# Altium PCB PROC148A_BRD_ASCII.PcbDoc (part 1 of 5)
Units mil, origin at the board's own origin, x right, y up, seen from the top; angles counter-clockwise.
Board outline 7150 x 3764 mil, 4 copper layers (Top Layer, GND01, PWR/GND02, Bottom Layer), stack 60.96 mil thick; 312 components, 352 nets, 2206 pads, 423 vias.
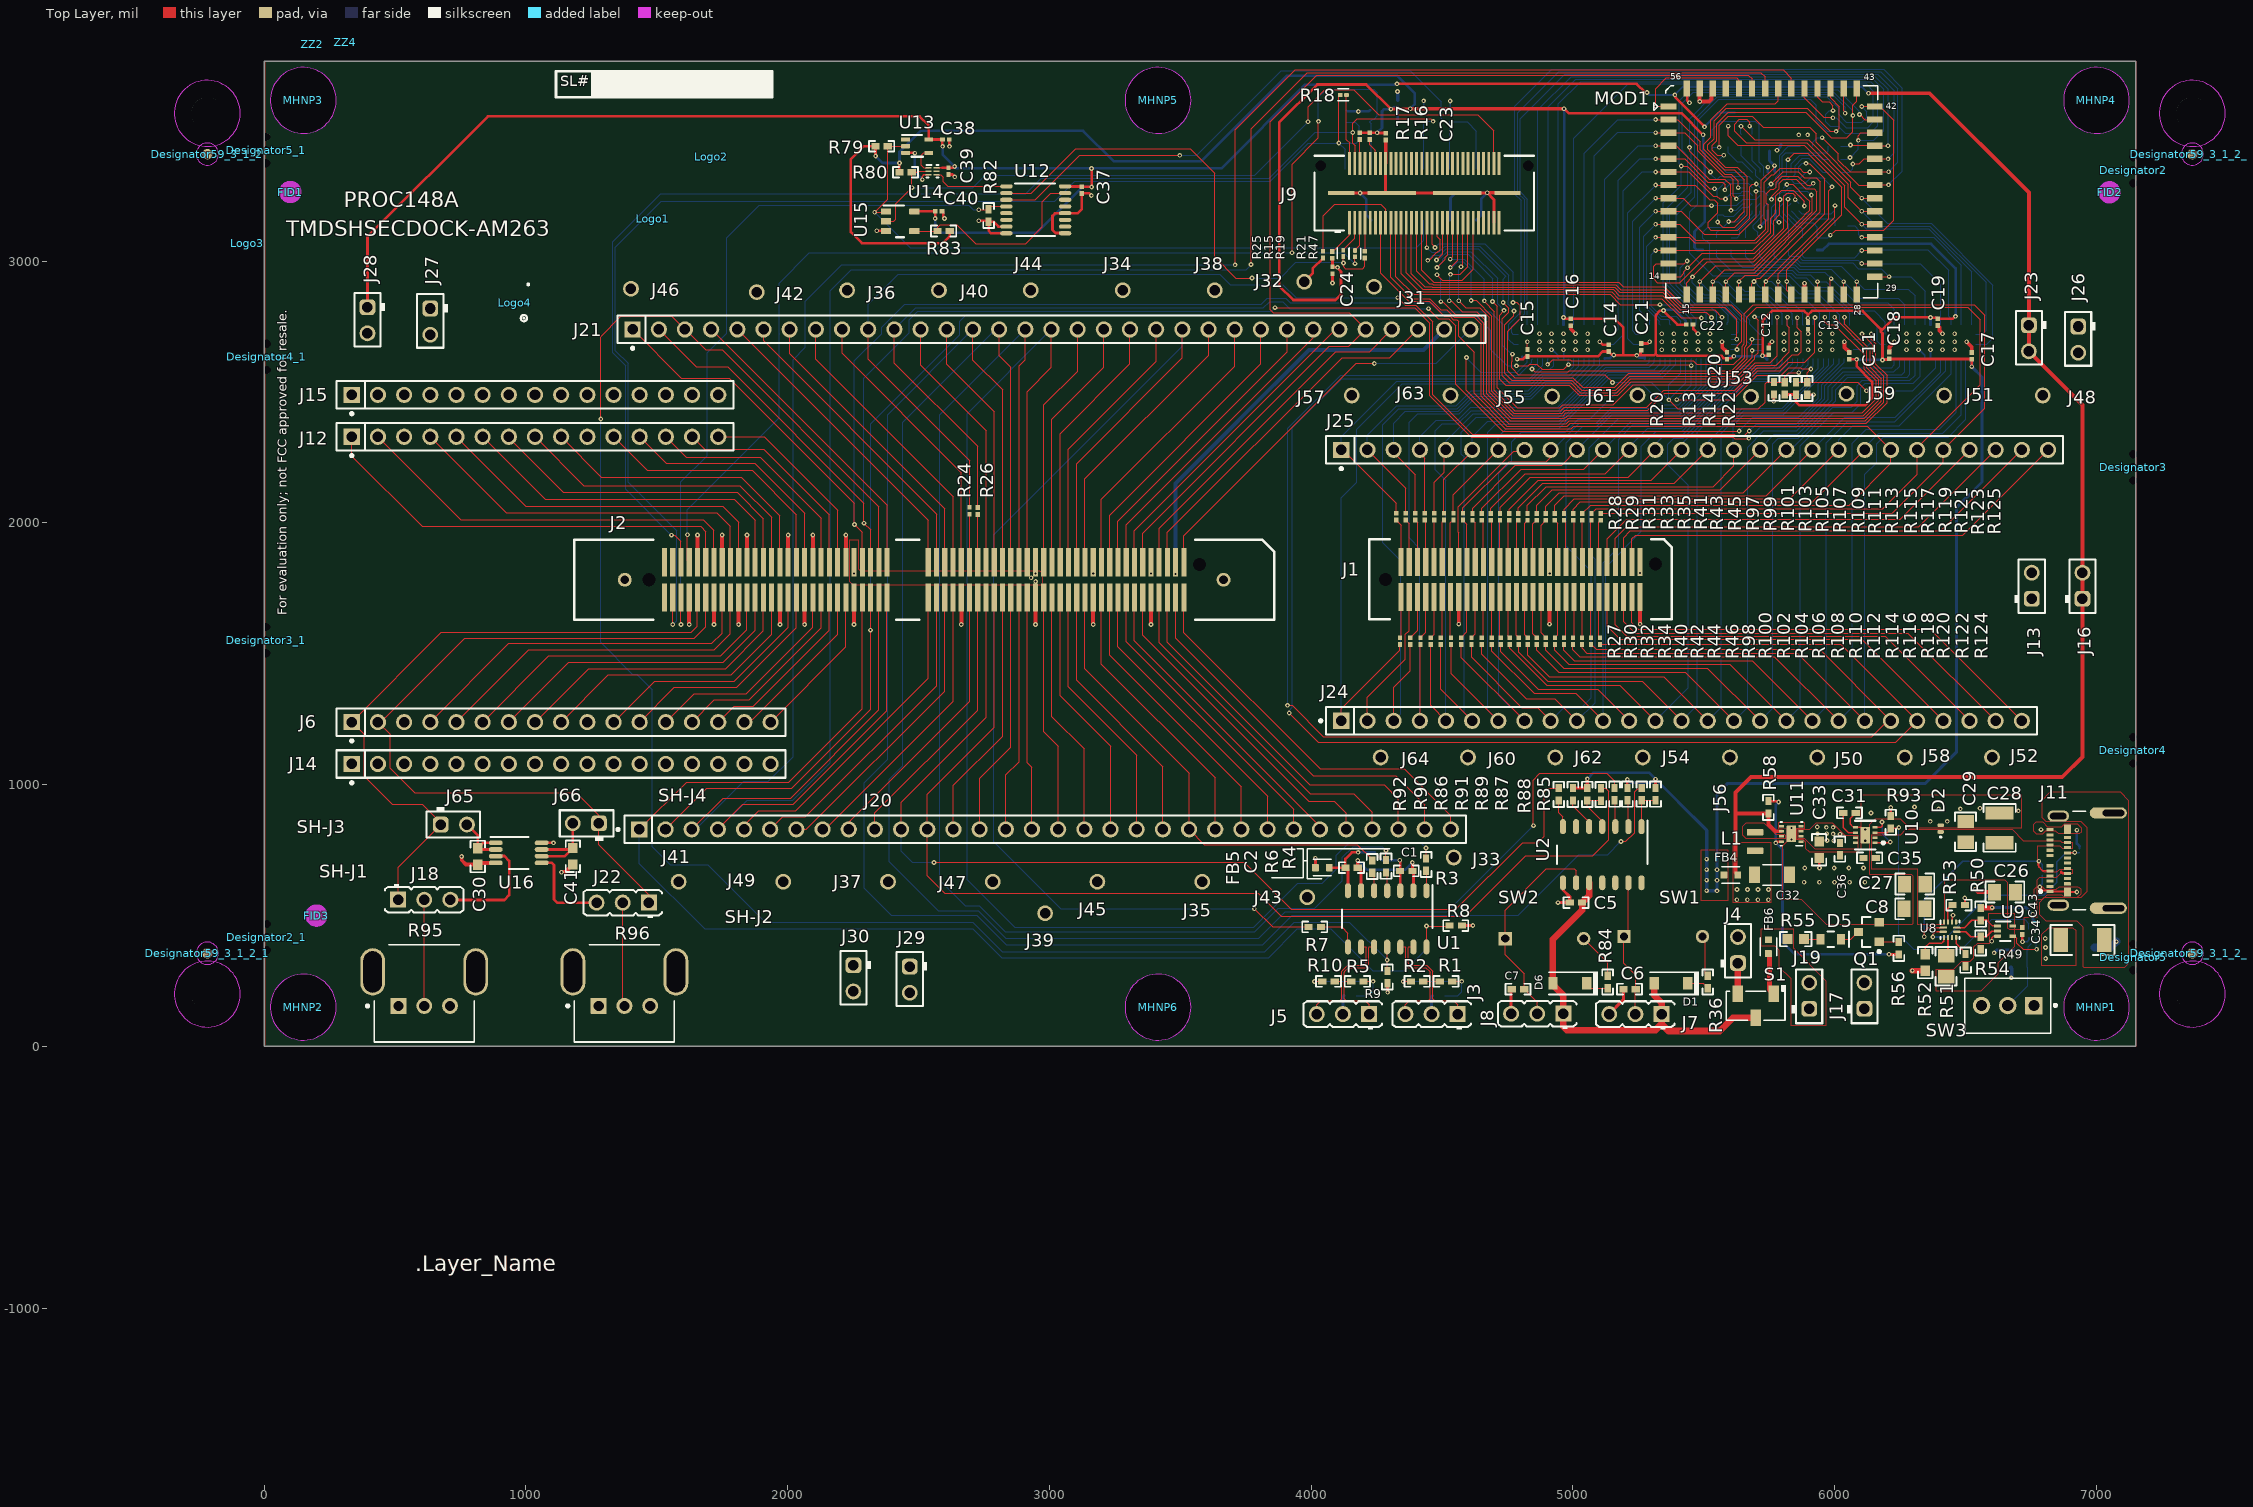
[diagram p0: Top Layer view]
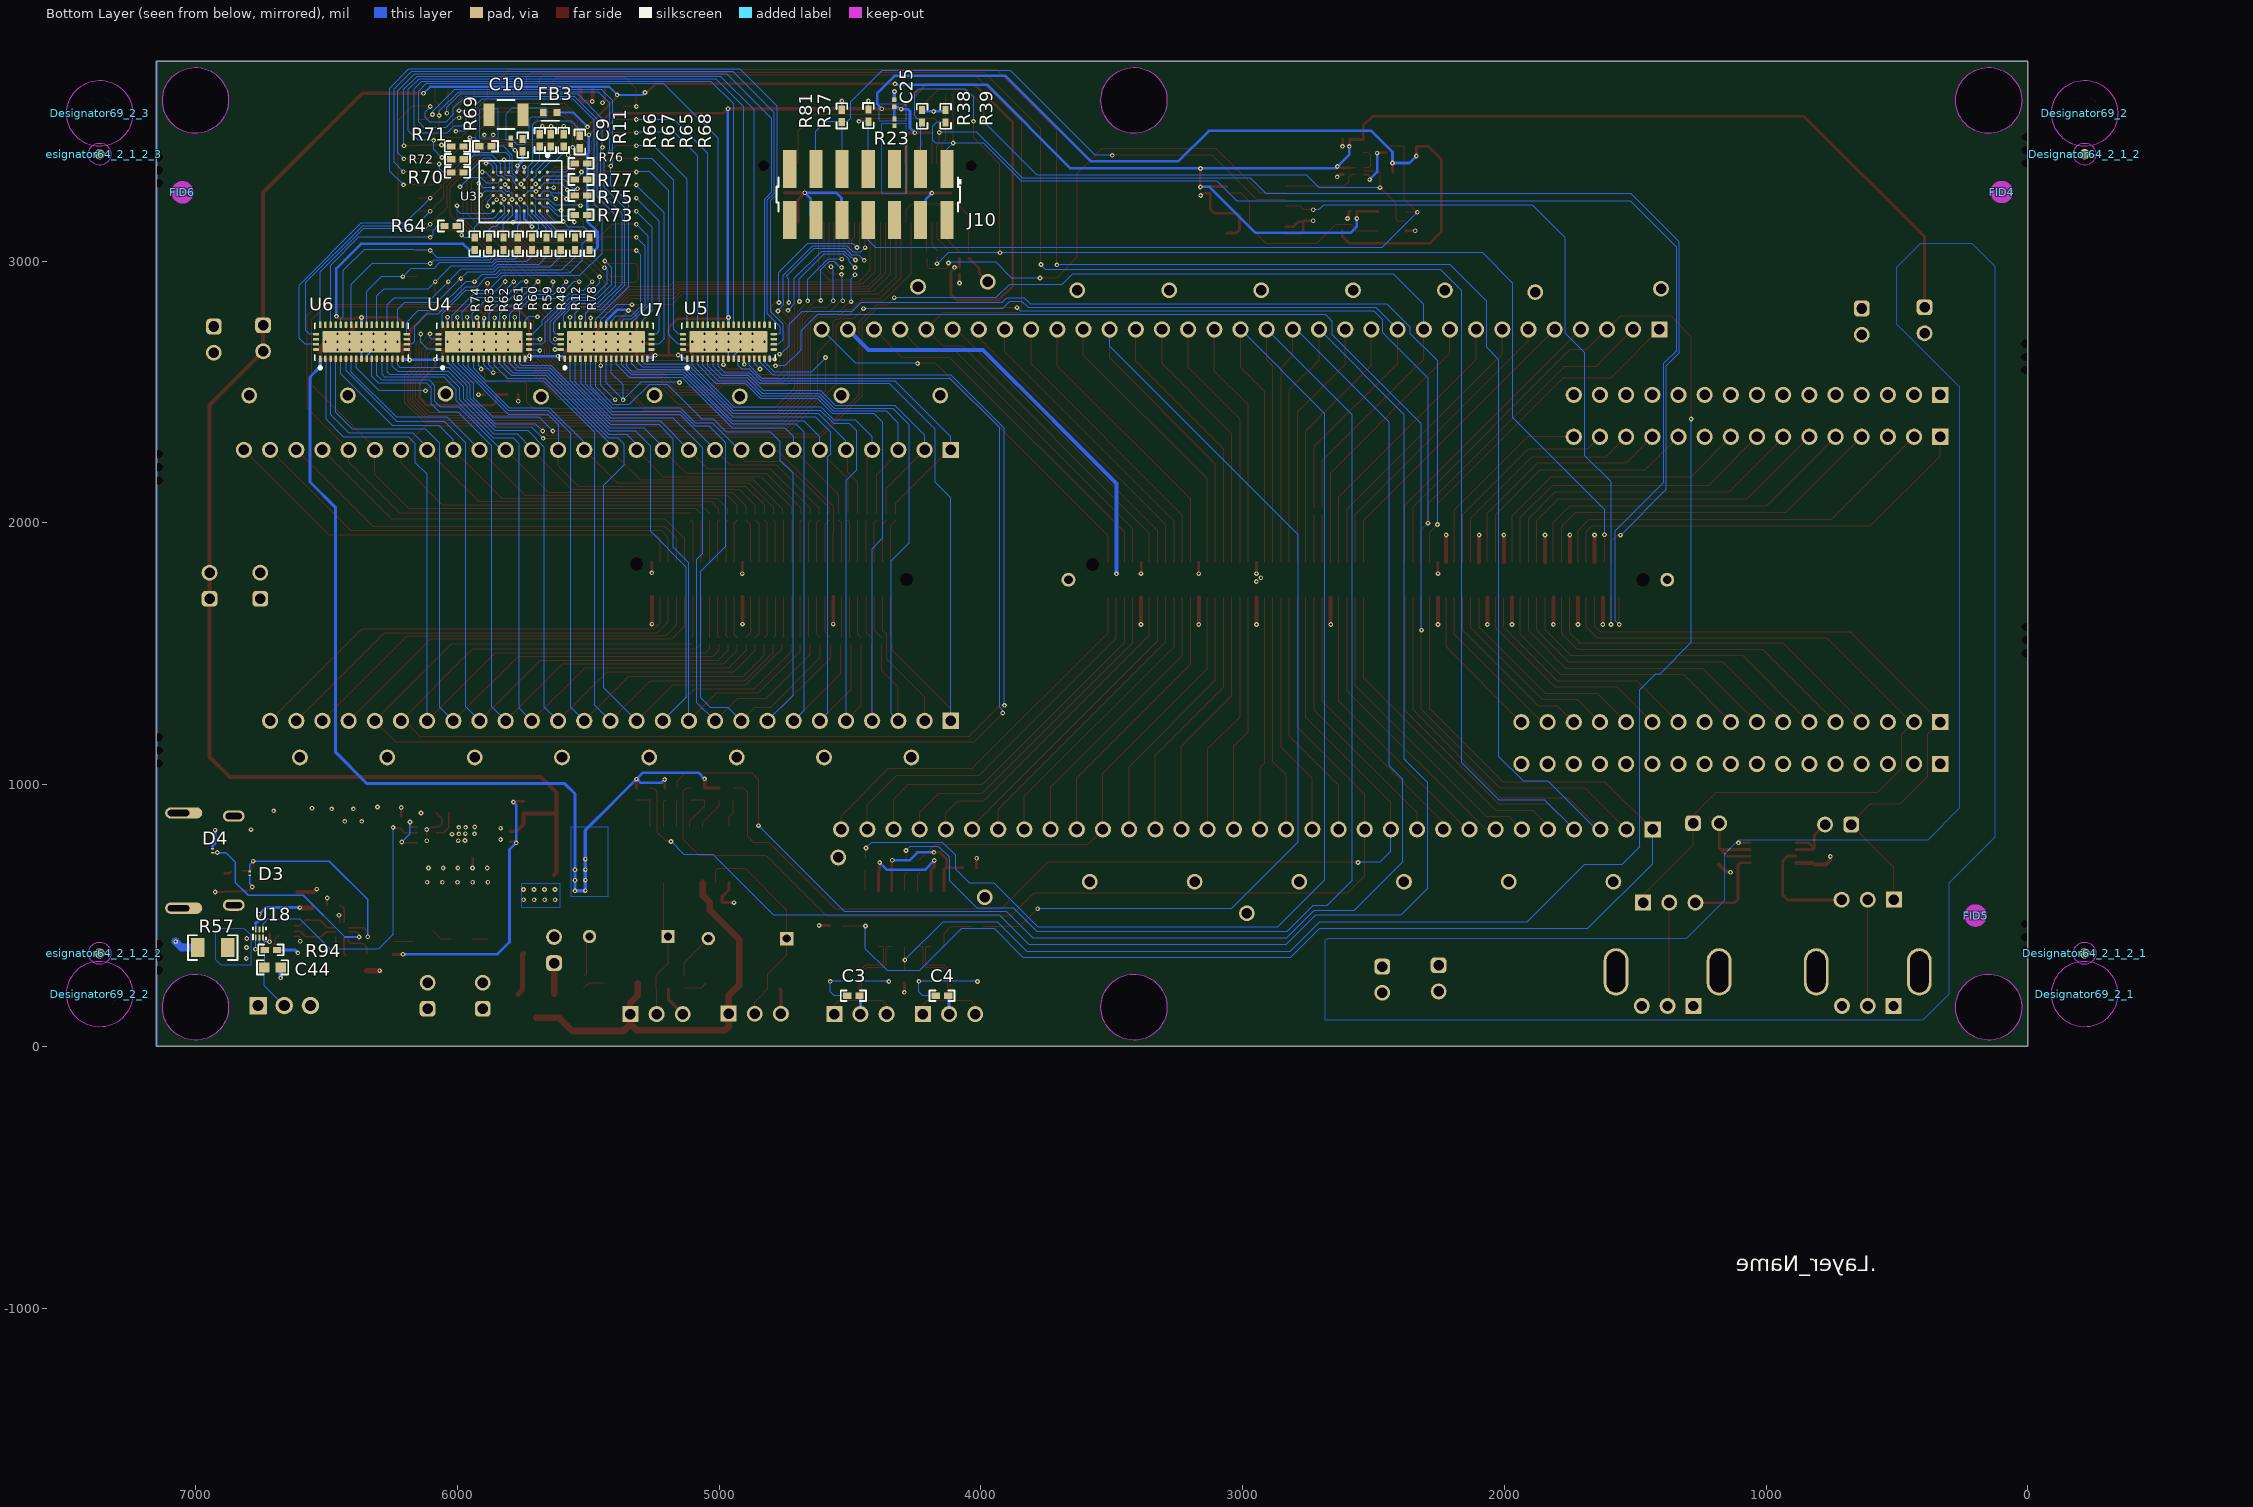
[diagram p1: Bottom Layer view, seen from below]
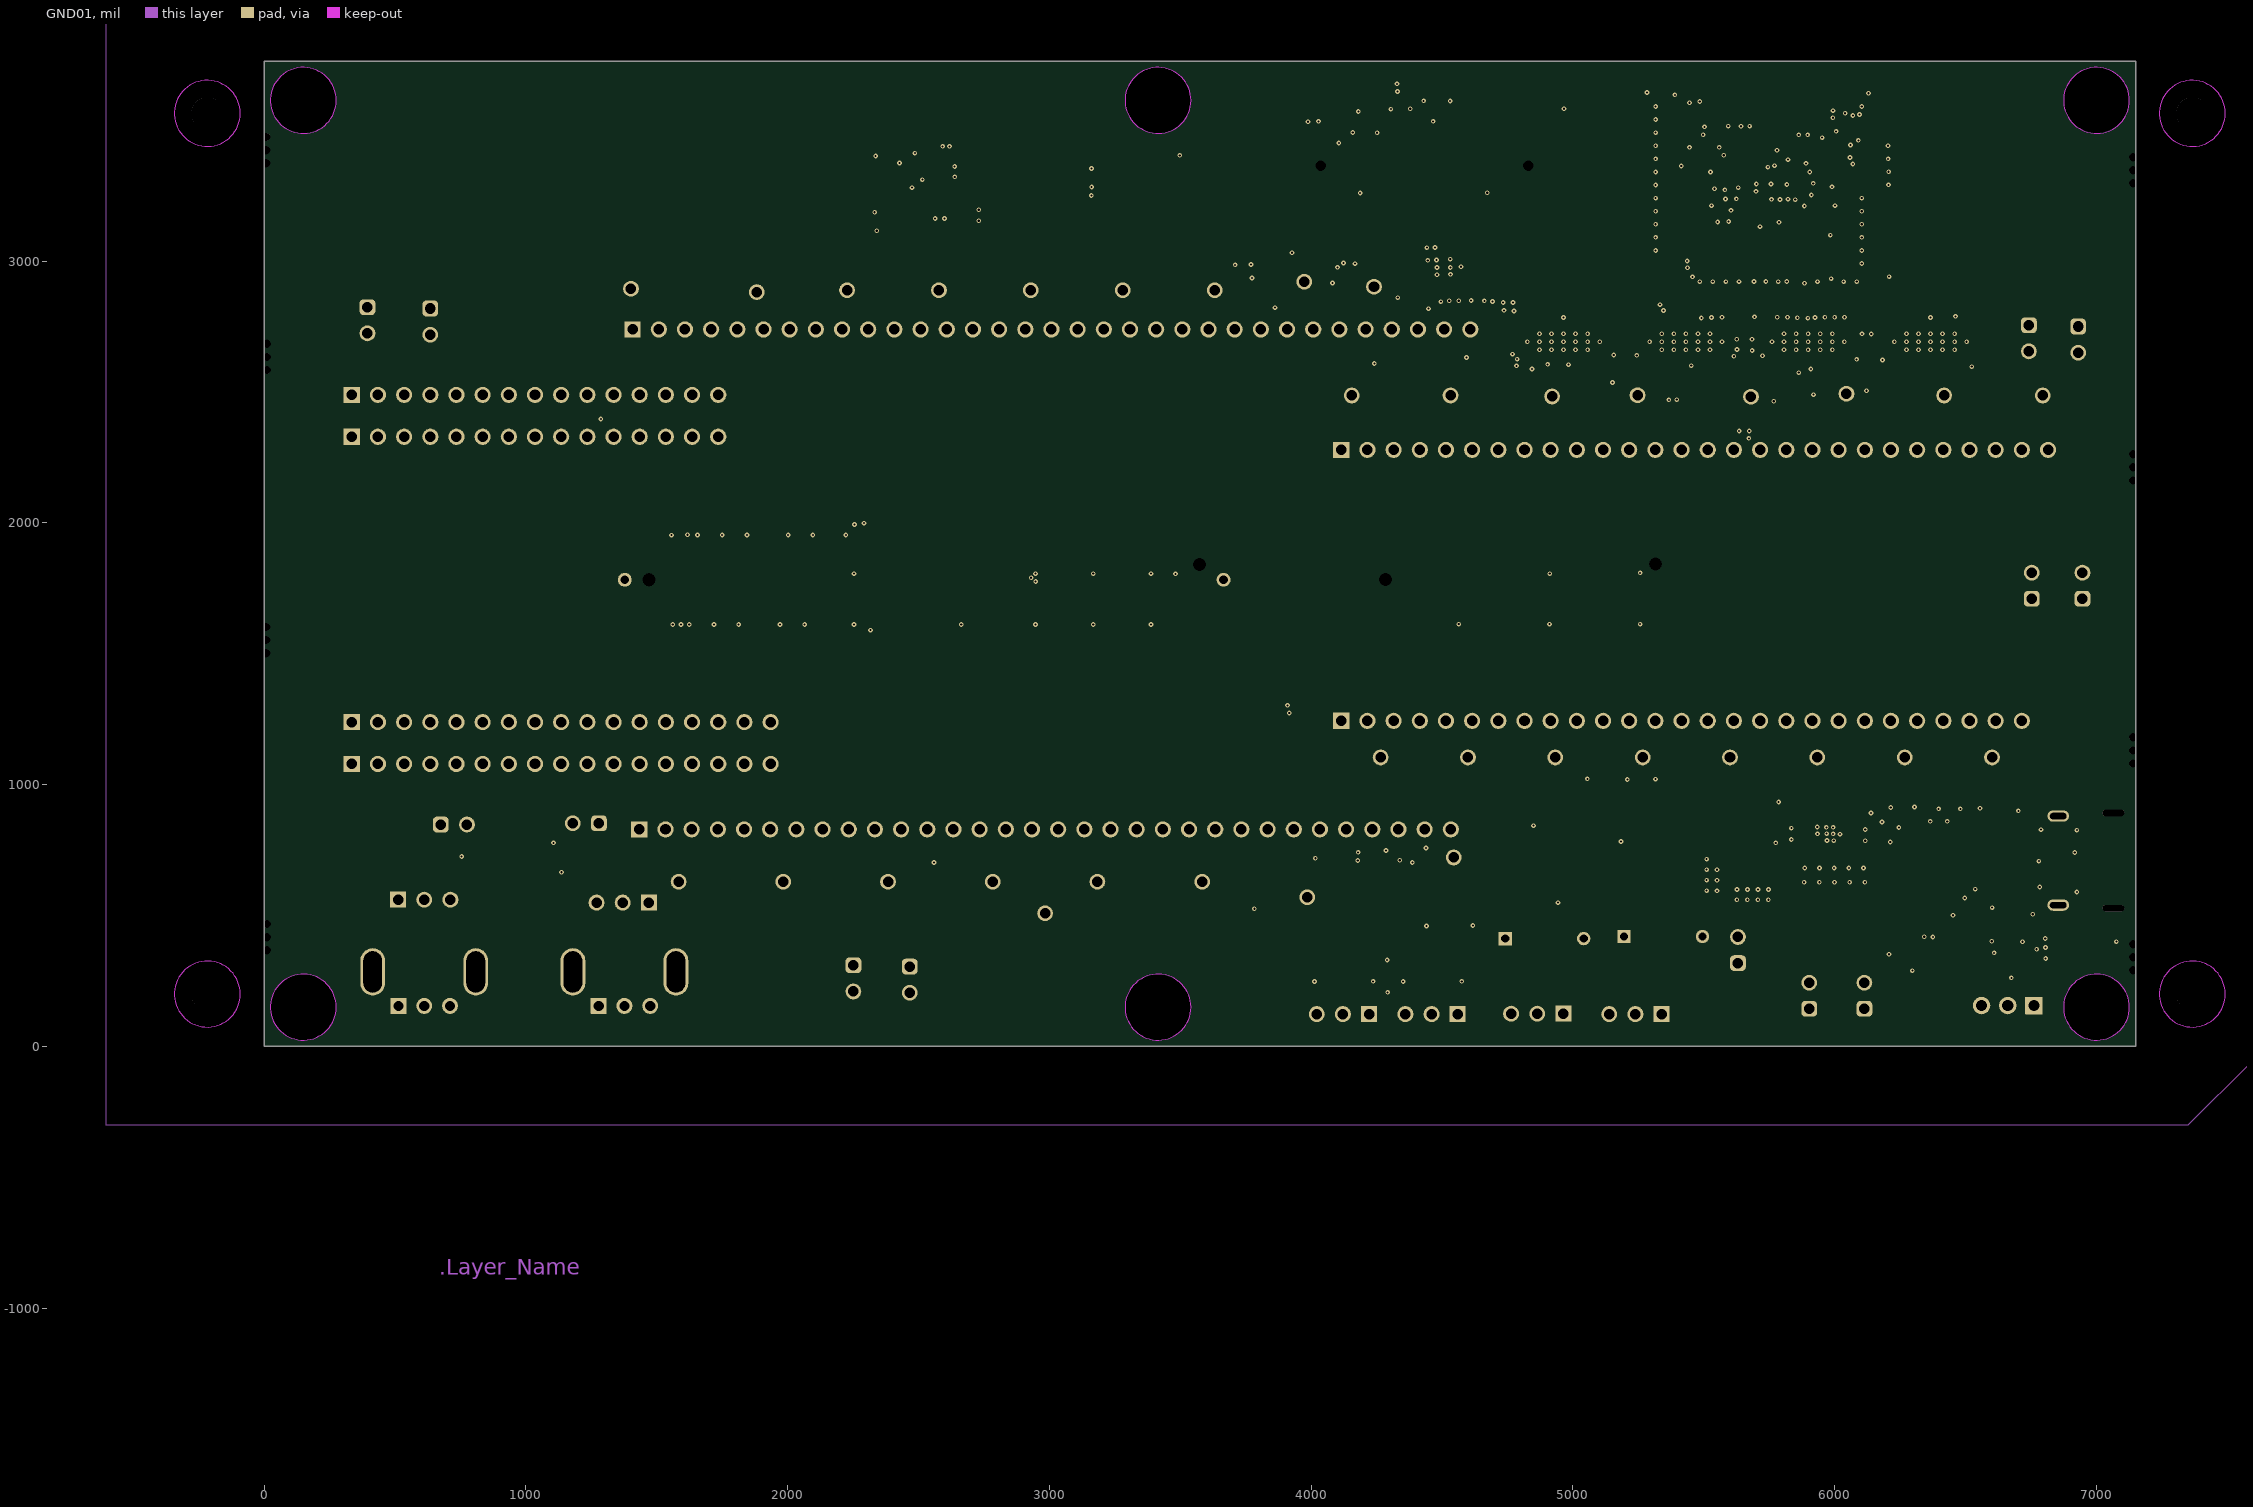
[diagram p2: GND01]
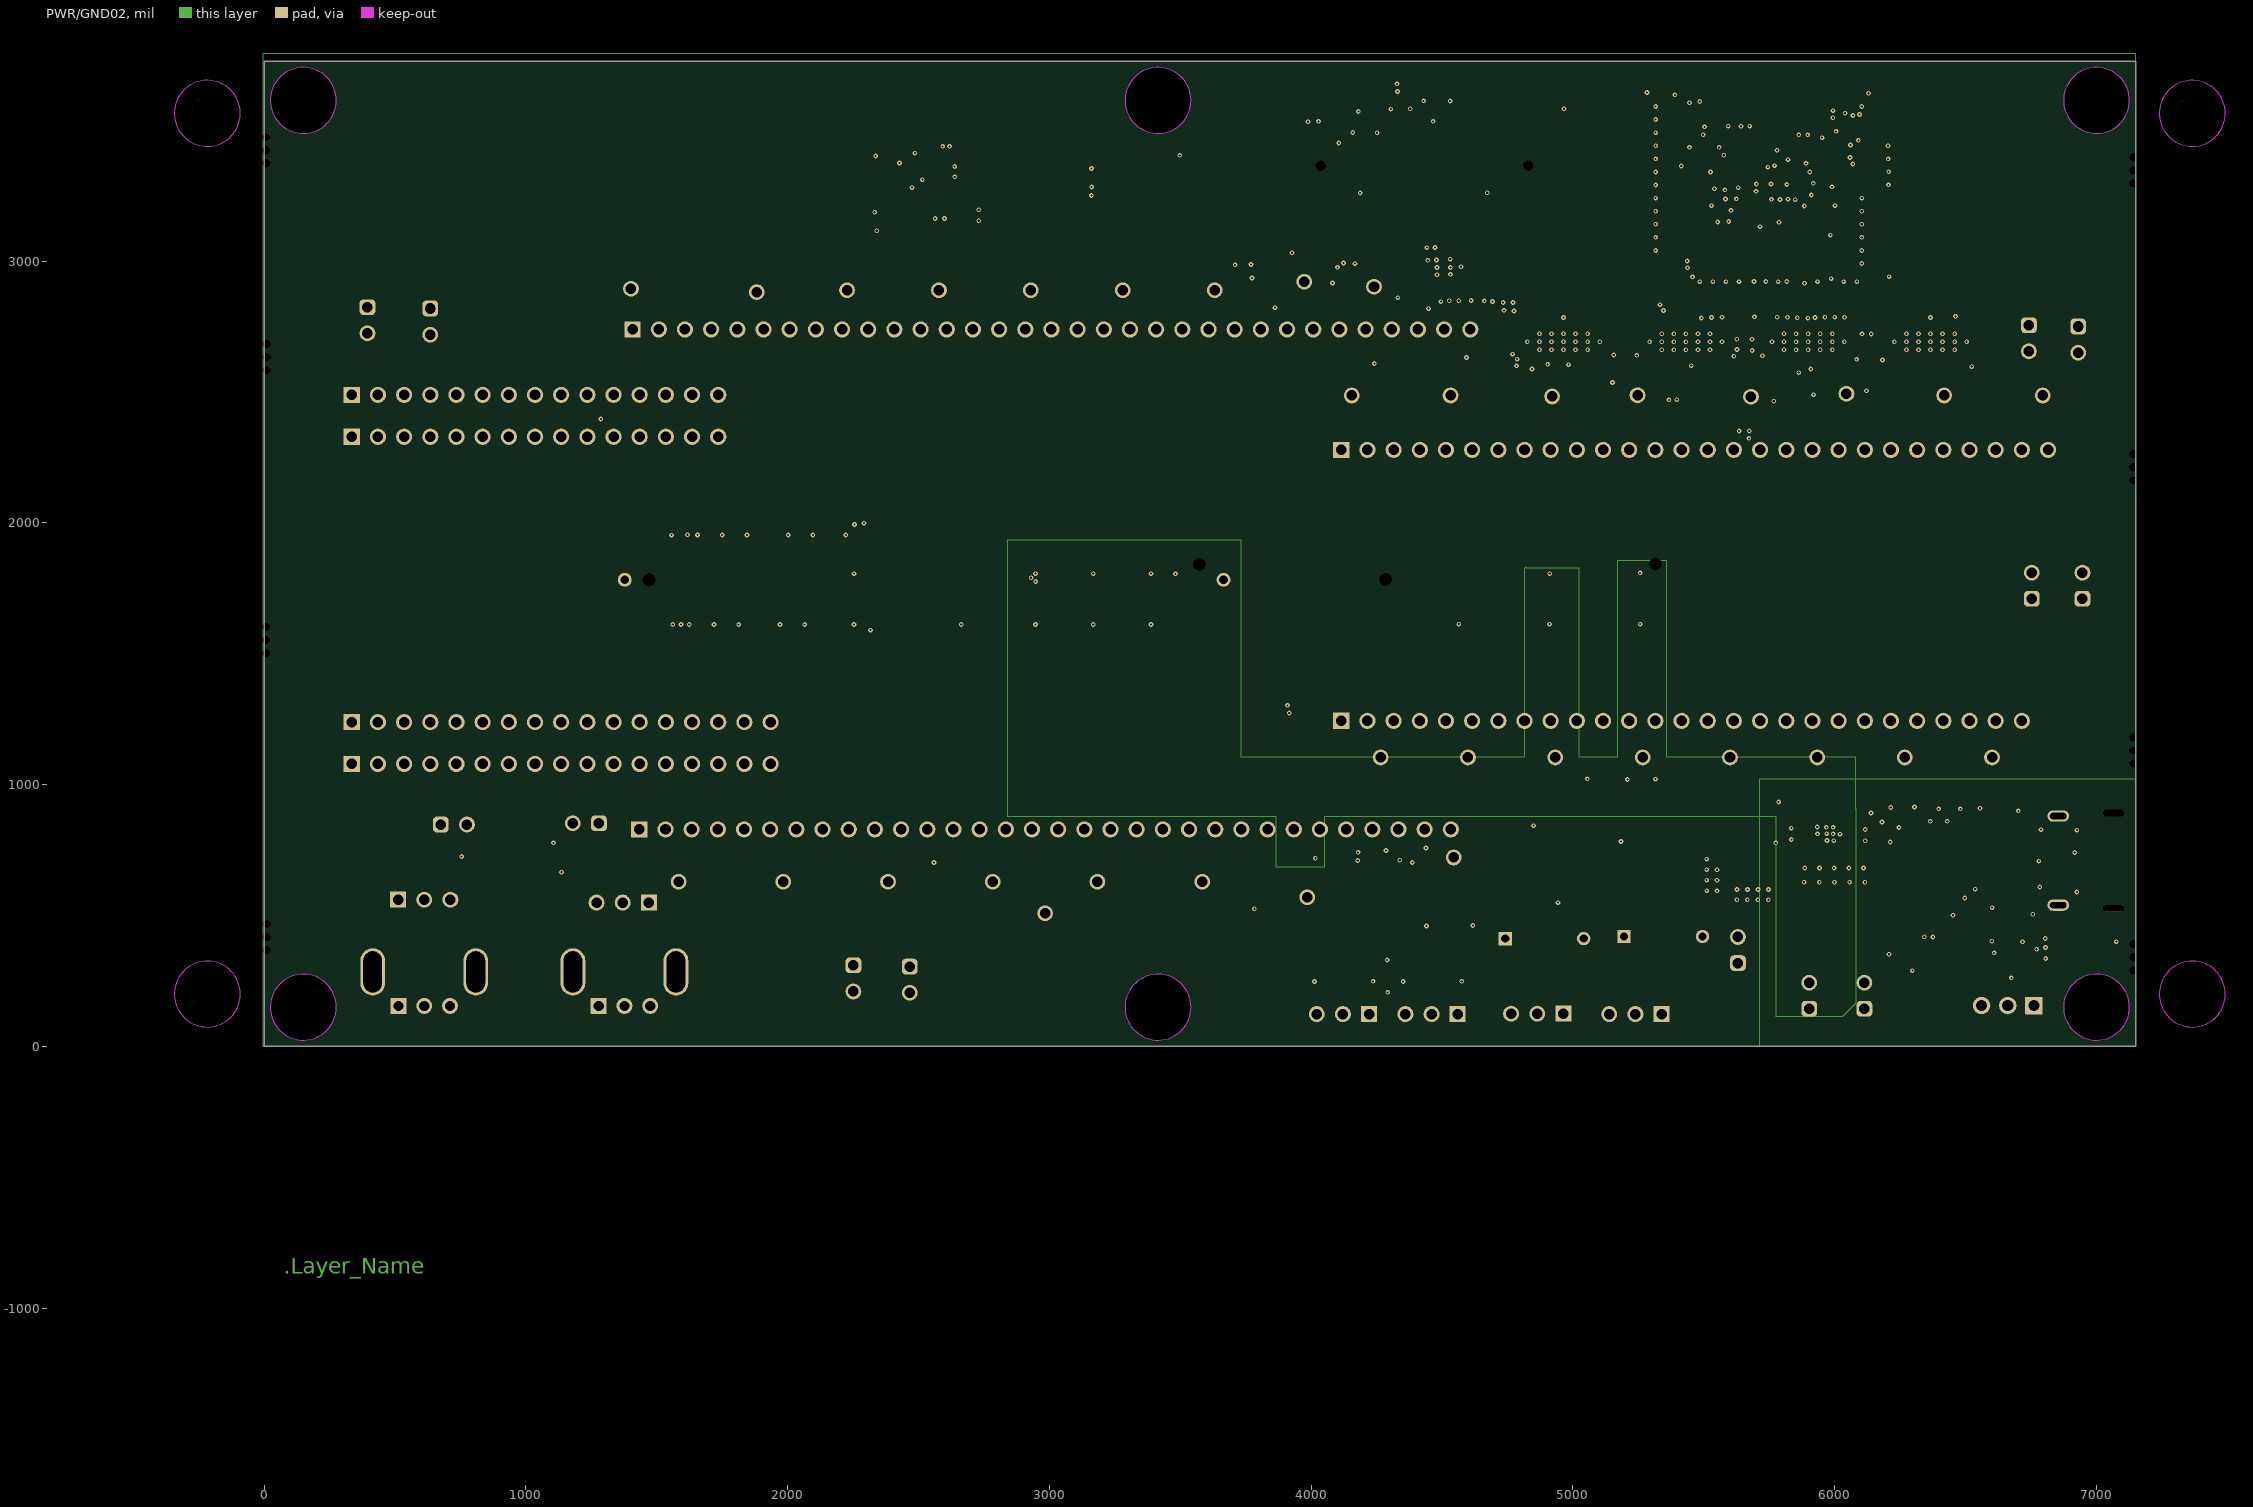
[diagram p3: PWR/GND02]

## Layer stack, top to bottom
Top Solder: solder mask 1, Solder Resist, Dk 3.5
Top Layer: signal copper 1.4
Dielectric 2: prepreg 3.7, FR-4, Dk 4.1
GND01: signal copper 1.38
Dielectric 1: dielectric 48, FR-4, Dk 4.8
PWR/GND02: signal copper 1.38
Dielectric 3: prepreg 3.7, FR-4, Dk 4.1
Bottom Layer: signal copper 1.4
Bottom Solder: solder mask 1, Solder Resist, Dk 3.5

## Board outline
-0.08,0 -0.08,3764 7149.92,3764 7149.92,0

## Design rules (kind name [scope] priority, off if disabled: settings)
AcuteAngle [All] p0: scope1count=1 scope1_0_kind=Board scope1_0_value=Board scope2count=1 scope2_0_kind=Board scope2_0_value=Board commentlength=0 minimum=4.50000000000000E+0001
AcuteAngle [All] p1: minimum=4.50000000000000E+0001 checktracksonly=FALSE
AssemblyTestPointUsage [All] p0: scope1count=1 scope1_0_kind=Board scope1_0_value=Board scope2count=1 scope2_0_kind=Board scope2_0_value=Board commentlength=0
AssemblyTestPointUsage [All] p1: valid=2
AssemblyTestpoint [All] p0: scope1count=1 scope1_0_kind=Board scope1_0_value=Board scope2count=1 scope2_0_kind=Board scope2_0_value=Board commentlength=0
BoardOutlineClearance [All] p0 off: scope1count=1 scope1_0_kind=Board scope1_0_value=Board scope2count=1 scope2_0_kind=Board scope2_0_value=Board commentlength=172 gap=40 // Protel DXP Scope 1 Expression Was: OnCopper and Not InComponentClass('Logo') and not InComponentClass('FiducialMark') and not InRegion(1000,500,4000,800) and not InPoly
BoardOutlineClearance BoardOutlineClearance_Poly [All] p0 off: scope1count=1 scope1_0_kind=Board scope1_0_value=Board scope2count=1 scope2_0_kind=Board scope2_0_value=Board commentlength=58 gap=25 // Protel DXP Scope 1 Expression Was: OnCopper and IsPoly
BoardOutlineClearance BoardOutlineClearance_MountingHoles [All] p0 off: scope1count=1 scope1_0_kind=Board scope1_0_value=Board scope2count=1 scope2_0_kind=Board scope2_0_value=Board commentlength=86 gap=40 // Protel DXP Scope 1 Expression Was: OnCopper and InComponentClass('Mounting Holes')
BoardOutlineClearance BoardOutlineClearance_1 [All] p0: scope1count=1 scope1_0_kind=Board scope1_0_value=Board scope2count=1 scope2_0_kind=Board scope2_0_value=Board commentlength=0 gap=30
BoardOutlineClearance BoardOutlineClearance_1 [All] p1: gap=30 ignorepadtopadclearanceinfootprint=FALSE
BoardOutlineClearance BoardOutlineClearance_MountingHoles [OnCopper and InComponentClass('Mounting Holes')] p2: gap=40 ignorepadtopadclearanceinfootprint=FALSE
BoardOutlineClearance BoardOutlineClearance_Poly [OnCopper and IsPoly] p3: gap=25 ignorepadtopadclearanceinfootprint=FALSE
BoardOutlineClearance [OnCopper and Not InComponentClass('Logo') and not InComponentClass('FiducialMark') and not InRegion(1000,500,4000,800) and not InPoly] p4: gap=40 ignorepadtopadclearanceinfootprint=FALSE
Clearance [All] p0: scope1count=1 scope1_0_kind=Board scope1_0_value=Board scope2count=1 scope2_0_kind=Board scope2_0_value=Board commentlength=0 gap=7.87
Clearance Clearance_FiducialMark [All] p0 off: scope1count=1 scope1_0_kind=Board scope1_0_value=Board scope2count=1 scope2_0_kind=Board scope2_0_value=Board commentlength=81 gap=8 // Protel DXP Scope 2 Expression Was: IsPad and InComponentClass('FiducialMark')
Clearance Clearance_Poly [All] p0 off: scope1count=1 scope1_0_kind=Board scope1_0_value=Board scope2count=1 scope2_0_kind=Board scope2_0_value=Board commentlength=48 gap=10 // Protel DXP Scope 1 Expression Was: InPolygon
Clearance Clearance_Keepouts [All] p0 off: scope1count=1 scope1_0_kind=Board scope1_0_value=Board scope2count=1 scope2_0_kind=Board scope2_0_value=Board commentlength=99 gap=0 // Protel DXP Scope 2 Expression Was: ((IsTrack Or IsArc) And Not InPoly) And IsFree and IsKeepOut
Clearance Clearance_room [All] p0 off: scope1count=1 scope1_0_kind=Board scope1_0_value=Board scope2count=1 scope2_0_kind=Board scope2_0_value=Board commentlength=67 gap=7.87 // Protel DXP Scope 1 Expression Was: WithinRoom('RoomDefinition')
Clearance Clearance_room [WithinRoom('RoomDefinition')] p1: gap=7.87 ignorepadtopadclearanceinfootprint=TRUE except(4: Arc-Arc Arc-Track Track-Track Track-SMDPad Track-Via SMDPad-Via)
Clearance Clearance_Keepouts [((IsTrack Or IsArc) And Not InPoly) And IsFree and IsKeepOut vs ((IsTrack Or IsArc) And Not InPoly) And IsFree and IsKeepOut] p2: gap=0 ignorepadtopadclearanceinfootprint=FALSE
Clearance Clearance_Poly [InPolygon] p3: gap=10 ignorepadtopadclearanceinfootprint=TRUE
Clearance Clearance_FiducialMark [IsKeepOut and InComponentClass('FiducialMark') vs IsPad and InComponentClass('FiducialMark')] p4: gap=8 ignorepadtopadclearanceinfootprint=FALSE
Clearance [All] p5: gap=7.87 ignorepadtopadclearanceinfootprint=TRUE except(5: Arc-Arc Arc-Track Track-Track; 6: SMDPad-Via; 7: Arc-SMDPad Track-SMDPad)
ComponentClearance [All] p0: scope1count=1 scope1_0_kind=Board scope1_0_value=Board scope2count=1 scope2_0_kind=Board scope2_0_value=Board commentlength=0 gap=20 collisioncheckmode=3
ComponentClearance ComponentClearance_THtoTH [All] p0 off: scope1count=1 scope1_0_kind=Board scope1_0_value=Board scope2count=1 scope2_0_kind=Board scope2_0_value=Board commentlength=54 gap=20 collisioncheckmode=3 // Protel DXP Scope 2 Expression Was: IsThruComponent
ComponentClearance ComponentClearance_THtoSMT [All] p0 off: scope1count=1 scope1_0_kind=Board scope1_0_value=Board scope2count=1 scope2_0_kind=Board scope2_0_value=Board commentlength=53 gap=30 collisioncheckmode=3 // Protel DXP Scope 2 Expression Was: IsSMTComponent
ComponentClearance ComponentClearance_SmallPassives [All] p0 off: scope1count=1 scope1_0_kind=Board scope1_0_value=Board scope2count=1 scope2_0_kind=Board scope2_0_value=Board commentlength=508 gap=14.96 collisioncheckmode=3 // Protel DXP Scope 2 Expression Was: HasFootprint('0201*') or HasFootprint('0402*') or HasFootprint('0508') or HasFootprint('0603*') or HasFootprint('0612') or HasFootprint('0805*') or HasFootprint('0815*') or HasFootprint('0830*') or HasFootprint('1206*') or HasFootprint('1210*') or HasFootprint('1808*') or HasFootprint('1812*') or HasFootprint('1825*') or HasFootprint('2010*') or HasFootprint('2220*') or HasFootprint('2225*') or HasFootprint('2512*') or HasFootprint('2728*') or HasFootprint('3518*')
ComponentClearance ComponentClearance_MountingHoles [All] p0: scope1count=1 scope1_0_kind=ComponentClass scope1_0_value="Mounting Holes" scope2count=1 scope2_0_kind=Board scope2_0_value=Board commentlength=0 gap=100 collisioncheckmode=3
ComponentClearance ComponentClearance_ScrewToNut [All] p0 off: scope1count=1 scope1_0_kind=Board scope1_0_value=Board scope2count=1 scope2_0_kind=Board scope2_0_value=Board commentlength=71 gap=5 collisioncheckmode=3 // Protel DXP Scope 2 Expression Was: (HasFootprint('Keystone_1902C'))
ComponentClearance ComponentClearance_Logo [All] p0: scope1count=1 scope1_0_kind=ComponentClass scope1_0_value=Logo scope2count=1 scope2_0_kind=Board scope2_0_value=Board commentlength=0 gap=30 collisioncheckmode=3
ComponentClearance ComponentClearance_Shunt [All] p0: scope1count=1 scope1_0_kind=ComponentClass scope1_0_value=Header scope2count=1 scope2_0_kind=ComponentClass scope2_0_value=Shunt commentlength=0 gap=0 collisioncheckmode=3
ComponentClearance ComponentClearance_MountingHoles_FiducialMarks [All] p0: scope1count=1 scope1_0_kind=ComponentClass scope1_0_value="Mounting Holes" scope2count=1 scope2_0_kind=ComponentClass scope2_0_value=FiducialMark commentlength=0 gap=50 collisioncheckmode=3
ComponentClearance ComponentClearance_MountingHoles_FiducialMarks [InComponentClass('Mounting Holes') vs InComponentClass('FiducialMark')] p1: gap=50 collisioncheckmode=3 verticalgap=10 showdistances=FALSE
ComponentClearance ComponentClearance_Shunt [InComponentClass('Header') vs InComponentClass('Shunt')] p2: gap=0 collisioncheckmode=3 verticalgap=0 showdistances=FALSE
ComponentClearance ComponentClearance_Logo [InComponentClass('Logo')] p3: gap=30 collisioncheckmode=3 verticalgap=10 showdistances=FALSE
ComponentClearance ComponentClearance_ScrewToNut [(HasFootprint('NY PMS 440 0025 PH')) vs (HasFootprint('Keystone_1902C'))] p4: gap=5 collisioncheckmode=3 verticalgap=10 showdistances=FALSE
ComponentClearance ComponentClearance_MountingHoles [InComponentClass('Mounting Holes')] p5: gap=100 collisioncheckmode=3 verticalgap=100000 showdistances=FALSE
ComponentClearance ComponentClearance_SmallPassives [HasFootprint('0201*') or HasFootprint('0402*') or HasFootprint('0508') or HasFootprint('0603*') or HasFootprint('0612') or HasFootprint('0805*') or HasFootprint('0815*') or HasFootprint('0830*') or HasFootprint('1206*') or HasFootprint('1210*') or HasFootprint('1808*') or HasFootprint('1812*') or HasFootprint('1825*') or HasFootprint('2010*') or HasFootprint('2220*') or HasFootprint('2225*') or HasFootprint('2512*') or HasFootprint('2728*') or HasFootprint('3518*') vs HasFootprint('0201*') or HasFootprint('0402*') or HasFootprint('0508') or HasFootprint('0603*') or HasFootprint('0612') or HasFootprint('0805*') or HasFootprint('0815*') or HasFootprint('0830*') or HasFootprint('1206*') or HasFootprint('1210*') or HasFootprint('1808*') or HasFootprint('1812*') or HasFootprint('1825*') or HasFootprint('2010*') or HasFootprint('2220*') or HasFootprint('2225*') or HasFootprint('2512*') or HasFootprint('2728*') or HasFootprint('3518*')] p6: gap=14.96 collisioncheckmode=3 verticalgap=10 showdistances=FALSE
ComponentClearance ComponentClearance_THtoSMT [IsThruComponent vs IsSMTComponent] p7: gap=30 collisioncheckmode=3 verticalgap=30 showdistances=FALSE
ComponentClearance ComponentClearance_THtoTH [IsThruComponent vs IsThruComponent] p8: gap=20 collisioncheckmode=3 verticalgap=30 showdistances=FALSE
ComponentClearance [All] p9: gap=20 collisioncheckmode=3 verticalgap=10 showdistances=FALSE
DiffPairsRouting DiffPairsRouting_1 [All] p0: scope1count=1 scope1_0_kind=Board scope1_0_value=Board scope2count=1 scope2_0_kind=Board scope2_0_value=Board commentlength=0
DiffPairsRouting [All] p0: scope1count=1 scope1_0_kind=Board scope1_0_value=Board scope2count=1 scope2_0_kind=Board scope2_0_value=Board commentlength=0
DiffPairsRouting [All] p1: maxlimit=5 minlimit=5 mostfreqgap=5 toplayer_minwidth=4 toplayer_maxwidth=4 toplayer_prefwidth=4 midlayer1_minwidth=4 midlayer1_maxwidth=4 midlayer1_prefwidth=4 midlayer2_minwidth=4 midlayer2_maxwidth=4 midlayer2_prefwidth=4 bottomlayer_minwidth=4 bottomlayer_maxwidth=4 bottomlayer_prefwidth=4 maxuncoupledlength=1000
DiffPairsRouting DiffPairsRouting_1 [All] p2: maxlimit=10 minlimit=10 mostfreqgap=10 toplayer_minwidth=15 toplayer_maxwidth=15 toplayer_prefwidth=15 midlayer1_minwidth=15 midlayer1_maxwidth=15 midlayer1_prefwidth=15 midlayer2_minwidth=15 midlayer2_maxwidth=15 midlayer2_prefwidth=15 bottomlayer_minwidth=15 bottomlayer_maxwidth=15 bottomlayer_prefwidth=15 maxuncoupledlength=500
FabricationTestPointUsage TestPointUsage [All] p0: scope1count=1 scope1_0_kind=Board scope1_0_value=Board scope2count=1 scope2_0_kind=Board scope2_0_value=Board commentlength=0 valid=2 allowmultiple=FALSE
FabricationTestPointUsage TestPointUsage [All] p1: valid=2 allowmultiple=FALSE
FabricationTestpoint Testpoint [All] p0: scope1count=1 scope1_0_kind=Board scope1_0_value=Board scope2count=1 scope2_0_kind=Board scope2_0_value=Board commentlength=0 side=3 testpointundercomponent=TRUE minsize=40 maxsize=100 preferedsize=60 minholesize=0 maxholesize=40 preferedholesize=32 testpointgrid=1
FabricationTestpoint Testpoint [All] p1: side=3 testpointundercomponent=TRUE minsize=40 maxsize=100 preferedsize=60 minholesize=0 maxholesize=40 preferedholesize=32 testpointgrid=1 allowsidetop=TRUE allowsidebottom=TRUE usegrid=TRUE gridtolerance=0.01
FanoutControl Fanout_Small [All] p0 off: scope1count=1 scope1_0_kind=Board scope1_0_value=Board scope2count=1 scope2_0_kind=Board scope2_0_value=Board commentlength=84 // Protel DXP Scope 1 Expression Was: (CompPinCount < 5)   Fanout_Small (Default Rule)
FanoutControl Fanout_Default [All] p0: scope1count=1 scope1_0_kind=Board scope1_0_value=Board scope2count=1 scope2_0_kind=Board scope2_0_value=Board commentlength=30 // Fanout_Default (Default Rule)
FanoutControl Fanout_SOIC [All] p0 off: scope1count=1 scope1_0_kind=Board scope1_0_value=Board scope2count=1 scope2_0_kind=Board scope2_0_value=Board commentlength=71 // Protel DXP Scope 1 Expression Was: IsSOIC   Fanout_SOIC (Default Rule)
FanoutControl Fanout_BGA [All] p0 off: scope1count=1 scope1_0_kind=Board scope1_0_value=Board scope2count=1 scope2_0_kind=Board scope2_0_value=Board commentlength=69 // Protel DXP Scope 1 Expression Was: IsBGA   Fanout_BGA (Default Rule)
FanoutControl Fanout_LCC [All] p0 off: scope1count=1 scope1_0_kind=Board scope1_0_value=Board scope2count=1 scope2_0_kind=Board scope2_0_value=Board commentlength=69 // Protel DXP Scope 1 Expression Was: IsLCC   Fanout_LCC (Default Rule)
FanoutControl Fanout_LCC [IsLCC] p1: bgadir=Out bgaviamode=Centered fanoutstyle=Auto fanoutdirection=Alternating viagrid=1 // Fanout_LCC (Default Rule)
FanoutControl Fanout_BGA [IsBGA] p2: bgadir=Out bgaviamode=Centered fanoutstyle=BGA fanoutdirection=Alternating viagrid=1 // Fanout_BGA (Default Rule)
FanoutControl Fanout_Default [All] p4: bgadir=Out bgaviamode=Centered fanoutstyle=Auto fanoutdirection=Alternating viagrid=1 // Fanout_Default (Default Rule)
FanoutControl Fanout_Small [(CompPinCount < 5)] p5: bgadir=Out bgaviamode=Centered fanoutstyle=Auto fanoutdirection=OutThenIn viagrid=1 // Fanout_Small (Default Rule)
Height [All] p0: scope1count=1 scope1_0_kind=Board scope1_0_value=Board scope2count=1 scope2_0_kind=Board scope2_0_value=Board commentlength=0
HoleSize [All] p0: scope1count=1 scope1_0_kind=Board scope1_0_value=Board scope2count=1 scope2_0_kind=Board scope2_0_value=Board commentlength=0 absolutevalues=TRUE maxlimit=251 minlimit=7.87 maxpercent=80.000 minpercent=20.000
HoleSize [All] p1: absolutevalues=TRUE maxlimit=251 minlimit=7.87 maxpercent=80.000 minpercent=20.000
HoleToHoleClearance [All] p0: scope1count=1 scope1_0_kind=Board scope1_0_value=Board scope2count=1 scope2_0_kind=Board scope2_0_value=Board commentlength=0
LayerPairs [All] p0: scope1count=1 scope1_0_kind=Board scope1_0_value=Board scope2count=1 scope2_0_kind=Board scope2_0_value=Board commentlength=0 enforce=TRUE
MinimumAnnularRing [All] p0: scope1count=1 scope1_0_kind=Board scope1_0_value=Board scope2count=1 scope2_0_kind=Board scope2_0_value=Board commentlength=0 minimumring=7.87
MinimumAnnularRing MinimumAnnularRing_ThermalPadVias [All] p0 off: scope1count=1 scope1_0_kind=Board scope1_0_value=Board scope2count=1 scope2_0_kind=Board scope2_0_value=Board commentlength=63 minimumring=5.91 // Protel DXP Scope 1 Expression Was: IsVia and InAnyComponent
MinimumAnnularRing MinimumAnnularRing_ThermalPadVias [IsVia and InAnyComponent] p1: minimumring=5.91
MinimumAnnularRing [All] p2: minimumring=7.87
MinimumSolderMaskSliver [All] p0: scope1count=1 scope1_0_kind=Board scope1_0_value=Board scope2count=1 scope2_0_kind=Board scope2_0_value=Board commentlength=0
MinimumSolderMaskSliver MinimumSolderMaskSliver_Logo [All] p0: scope1count=1 scope1_0_kind=ComponentClass scope1_0_value=Logo scope2count=1 scope2_0_kind=ComponentClass scope2_0_value=Logo commentlength=0
MinimumSolderMaskSliver MinimumSolderMaskSliver_Logo [InComponentClass('Logo') vs InComponentClass('Logo')] p1: minsoldermaskwidth=0.7
MinimumSolderMaskSliver [All] p2: minsoldermaskwidth=3.94
NetAntennae [All] p0: scope1count=1 scope1_0_kind=Board scope1_0_value=Board scope2count=1 scope2_0_kind=Board scope2_0_value=Board commentlength=0
PasteMaskExpansion [All] p0: scope1count=1 scope1_0_kind=Board scope1_0_value=Board scope2count=1 scope2_0_kind=Board scope2_0_value=Board commentlength=0 expansion=0
PlaneClearance [All] p0: scope1count=1 scope1_0_kind=Board scope1_0_value=Board scope2count=1 scope2_0_kind=Board scope2_0_value=Board commentlength=0 clearance=20
PlaneConnect [All] p0: scope1count=1 scope1_0_kind=Board scope1_0_value=Board scope2count=1 scope2_0_kind=Board scope2_0_value=Board commentlength=0 planeconnectstyle=Relief reliefexpansion=10 reliefentries=4 reliefconductorwidth=10 reliefairgap=10
PlaneConnect [All] p1: planeconnectstyle=Relief reliefexpansion=10 reliefentries=4 reliefconductorwidth=10 reliefairgap=10
PolygonConnect [All] p0: scope1count=1 scope1_0_kind=Board scope1_0_value=Board scope2count=1 scope2_0_kind=Board scope2_0_value=Board commentlength=0 connectstyle=Direct reliefconductorwidth=10 reliefentries=4 polygonreliefangle="90 Angle"
PolygonConnect [All] p1: connectstyle=Direct reliefconductorwidth=10 reliefentries=4 polygonreliefangle="90 Angle" airgapwidth=10
RoomDefinition [All] p0: scope1count=1 scope1_0_kind=Board scope1_0_value=Board scope2count=1 scope2_0_kind=Board scope2_0_value=Board commentlength=0 region_x1=66200000 region_y1=41700000 region_x2=68850000 region_y2=43648200 confinementstyle=ConfineOut
RoomDefinition [All vs False] p1: confinementstyle=ConfineOut formatcopy=TRUE lockcomponents=FALSE outline 5885,3364.82 5885,3170 5620,3170 5620,3364.82
RoutingCorners [All] p0: scope1count=1 scope1_0_kind=Board scope1_0_value=Board scope2count=1 scope2_0_kind=Board scope2_0_value=Board commentlength=0 cornerstyle=45-Degree minsetback=100 maxsetback=100
RoutingLayers [All] p0: scope1count=1 scope1_0_kind=Board scope1_0_value=Board scope2count=1 scope2_0_kind=Board scope2_0_value=Board commentlength=0 top layer=Automatic mid layer 1=Automatic mid layer 2=Automatic bottom layer=Automatic
RoutingLayers [All] p1: top layer_v5=TRUE mid layer 1_v5=FALSE mid layer 2_v5=FALSE bottom layer_v5=TRUE
RoutingPriority [All] p0: scope1count=1 scope1_0_kind=Board scope1_0_value=Board scope2count=1 scope2_0_kind=Board scope2_0_value=Board commentlength=0
RoutingTopology [All] p0: scope1count=1 scope1_0_kind=Board scope1_0_value=Board scope2count=1 scope2_0_kind=Board scope2_0_value=Board commentlength=0 topology=Shortest
RoutingVias ThermalPadVias [All] p0 off: scope1count=1 scope1_0_kind=Board scope1_0_value=Board scope2count=1 scope2_0_kind=Board scope2_0_value=Board commentlength=63 holewidth=7.87 width=19.68 viastyle="Through Hole" minholewidth=7.87 minwidth=19.68 maxholewidth=12.99 maxwidth=23.62 // Protel DXP Scope 1 Expression Was: IsVia and InAnyComponent
RoutingVias RoutingVias_1 [All] p0: scope1count=1 scope1_0_kind=NetClass scope1_0_value="All Nets" scope2count=1 scope2_0_kind=Board scope2_0_value=Board commentlength=0 holewidth=28 width=50 viastyle="Through Hole" minholewidth=28 minwidth=50 maxholewidth=28 maxwidth=50
RoutingVias [All] p0: scope1count=1 scope1_0_kind=Board scope1_0_value=Board scope2count=1 scope2_0_kind=Board scope2_0_value=Board commentlength=0 holewidth=8 width=18 viastyle="Through Hole" minholewidth=8 minwidth=18 maxholewidth=8 maxwidth=18
RoutingVias [All] p1: holewidth=8 width=18 viastyle="Through Hole" minholewidth=8 minwidth=18 maxholewidth=8 maxwidth=18
RoutingVias RoutingVias_1 [InNetClass('All Nets')] p2: holewidth=28 width=50 viastyle="Through Hole" minholewidth=28 minwidth=50 maxholewidth=28 maxwidth=50
RoutingVias ThermalPadVias [IsVia and InAnyComponent] p3: holewidth=7.87 width=19.68 viastyle="Through Hole" minholewidth=7.87 minwidth=19.68 maxholewidth=12.99 maxwidth=23.62
ShortCircuit [All] p0: scope1count=1 scope1_0_kind=Board scope1_0_value=Board scope2count=1 scope2_0_kind=Board scope2_0_value=Board commentlength=0 allowed=FALSE
SilkToBoardRegionClearance [All] p0: scope1count=1 scope1_0_kind=Board scope1_0_value=Board scope2count=1 scope2_0_kind=Board scope2_0_value=Board commentlength=0
SilkToSilkClearance [All] p0: scope1count=1 scope1_0_kind=Board scope1_0_value=Board scope2count=1 scope2_0_kind=Board scope2_0_value=Board commentlength=0
SilkToSilkClearance SilkToSilkClearance_Pb-FreeLogo [All] p0 off: scope1count=1 scope1_0_kind=Board scope1_0_value=Board scope2count=1 scope2_0_kind=Board scope2_0_value=Board commentlength=120 // Protel DXP Scope 2 Expression Was: (HasFootprint('Pb-Free_Overlay_Medium') OR HasFootprint('Pb-Free_Overlay_Small'))
SilkToSilkClearance SilkToSilkClearance_Pb-FreeLogo [(HasFootprint('Pb-Free_Overlay_Medium') OR HasFootprint('Pb-Free_Overlay_Small')) vs (HasFootprint('Pb-Free_Overlay_Medium') OR HasFootprint('Pb-Free_Overlay_Small'))] p1: silktosilkclearance=0
SilkToSilkClearance [All] p2: silktosilkclearance=3.94
SilkToSolderMaskClearance "Silk to Solder Mask Opening" [All] p0: scope1count=1 scope1_0_kind=Board scope1_0_value=Board scope2count=1 scope2_0_kind=Board scope2_0_value=Board commentlength=0
SilkToSolderMaskClearance SilkToComponentPadClearance [All] p0 off: scope1count=1 scope1_0_kind=Board scope1_0_value=Board scope2count=1 scope2_0_kind=Board scope2_0_value=Board commentlength=87 // Protel DXP Scope 1 Expression Was: (IsPad or IsFill or IsRegion) and InAnycomponent
SilkToSolderMaskClearance SilkToComponentPadClearance [(IsPad or IsFill or IsRegion) and InAnycomponent] p1: minsilkscreentomaskgap=5 clearancetoexposedcopper=TRUE
SilkToSolderMaskClearance "Silk to Solder Mask Opening" [All] p2: minsilkscreentomaskgap=3.94 clearancetoexposedcopper=FALSE
SolderMaskExpansion [All] p0: scope1count=1 scope1_0_kind=Board scope1_0_value=Board scope2count=1 scope2_0_kind=Board scope2_0_value=Board commentlength=0 expansion=1.97
SolderMaskExpansion [All] p1: expansion=1.97 istentingtop=FALSE
UnRoutedNet [All] p0: scope1count=1 scope1_0_kind=Board scope1_0_value=Board scope2count=1 scope2_0_kind=Board scope2_0_value=Board commentlength=0
UnRoutedNet [All] p1: checkbadconnections=TRUE
UnpouredPolygon [All] p0: scope1count=1 scope1_0_kind=Board scope1_0_value=Board scope2count=1 scope2_0_kind=Board scope2_0_value=Board commentlength=0
Width Width_2 [All] p0: scope1count=1 scope1_0_kind=Board scope1_0_value=Board scope2count=1 scope2_0_kind=Board scope2_0_value=Board commentlength=0 maxlimit=10 minlimit=4 preferedwidth=10
Width Width_1_BGA [All] p0 off: scope1count=1 scope1_0_kind=Board scope1_0_value=Board scope2count=1 scope2_0_kind=Board scope2_0_value=Board commentlength=85 maxlimit=10 minlimit=4 preferedwidth=10 // Protel DXP Scope 1 Expression Was: WithinRoom('RoomDefinition') and OnBottomLayer
Width [All] p0: scope1count=1 scope1_0_kind=Board scope1_0_value=Board scope2count=1 scope2_0_kind=Board scope2_0_value=Board commentlength=0 maxlimit=100 minlimit=4 preferedwidth=10
Width [All] p1: maxlimit=100 minlimit=4 preferedwidth=10 minimp=50.000000 maximp=50.000000 favimp=50.000000 checkconnectedcopper=TRUE
Width Width_1_BGA [WithinRoom('RoomDefinition') and OnBottomLayer] p2: maxlimit=10 minlimit=4 preferedwidth=10 toplayer_prefwidth=6 bottomlayer_prefwidth=6 minimp=50.000000 maximp=50.000000 favimp=50.000000
Width Width_2 [All] p3: maxlimit=10 minlimit=4 preferedwidth=10 minimp=50.000000 maximp=50.000000 favimp=50.000000
14 further rules are at their usual default settings.

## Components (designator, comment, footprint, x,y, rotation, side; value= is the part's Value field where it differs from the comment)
C1 "GRM155R71H104ME14D" 0402 4363.3,670.72 r0 top
C2 "GRM155R71H104ME14D" 0402 4154.41,682.92 r0 top
C3 "GRM155R72A472KA01D" 0402 4486.92,193.67 r180 bottom
C4 "GRM155R72A472KA01D" 0402 4148.4,193.67 r180 bottom
C5 "GRM155R71H104ME14D" 0402 5011.47,549.3 r180 top
C6 "CGA2B2X8R1H221K050BA" 0402 5216.38,218.72 r180 top
C7 "CGA2B2X8R1H221K050BA" 0402 4790,218.72 r180 top
C8 "C0805C104M5RACTU" 0805_HV 6305,525.7 r180 top
C9 "GRM033R61C104KE84D" 0201_033 5795.28,3457.77 r270 bottom
C10 "GRJ32ER71H106KE11L" 1210_280 5813.81,3559.69 r0 bottom
C11 "GRM033R61C104KE84D" 0201_033 6056.15,2638.35 r90 top
C12 "GRM033R61C104KE84D" 0201_033 5748.48,2654.85 r90 top
C13 "GRM033R61C104KE84D" 0201_033 5897.7,2752.4 r270 top
C14 "GRM033R61C104KE84D" 0201_033 5137.39,2667.55 r90 top
C15 "GRM033R61C104KE84D" 0201_033 4826.2,2648.99 r90 top
C16 "GRM033R61C104KE84D" 0201_033 4991.7,2766.4 r270 top
C17 "GRM033R61C104KE84D" 0201_033 6523.45,2638.35 r90 top
C18 "GRM033R61C104KE84D" 0201_033 6208.57,2639.88 r90 top
C19 "GRM033R61C104KE84D" 0201_033 6393.6,2766.77 r270 top
C20 "GRM033R61C104KE84D" 0201_033 5588.8,2638.4 r90 top
C21 "GRM033R61C104KE84D" 0201_033 5261.18,2672.5 r90 top
C22 "GRM033R61C104KE84D" 0201_033 5446.1,2757.6 r0 top
C23 "GRM033R61C104KE84D" 0201_033 4284.88,3475.55 r270 top
C24 "GRM033R61C104KE84D" 0201_033 4081.68,2965.16 r270 top
C25 "GRM033R61C104KE84D" 0201_033 4330.71,3603.13 r90 bottom
C26 "C0805C104M5RACTU" 0805_HV 6650,589.92 r180 top
C27 "C0805C104M5RACTU" 0805_HV 6306,620 r180 top
C28 "CL32B106KBJNNWE" 1210_270 6630,834.8 r90 top
C29 "C0805C104M5RACTU" 0805_HV 6500,820 r90 top
C30 "GRM1885C1H301JA01D" 0603 816.38,725.71 r270 top
C31 "GRM1555C1H102JA01D" 0402 6056.38,891.89 r0 top
C32 "GRM31CR71A226KE15L" 1206_180 5760.43,655 r0 top
C33 "GRT188R61E106ME13D" 0603 5940.74,751.5 r90 top
C34 "GR442QR73D102KW01L" 1808 6946.55,406.81 r0 top
C35 "GRM155R61E105KA12D" 0402 6133.62,720 r180 top
C36 "GRM155R61E105KA12D" 0402 6020,753.62 r270 top
C37 "GRM033R61C104KE84D" 0201_033 3124.18,3271.58 r270 top
C38 "GRM033R61C104KE84D" 0201_033 2604.29,3464.55 r0 top
C39 "GRM033R61C104KE84D" 0201_033 2614.29,3344.12 r270 top
C40 "GRM033R61C104KE84D" 0201_033 2576.96,3190.55 r0 top
C41 "GRM1885C1H301JA01D" 0603 1179.55,726.69 r270 top
C43 "GRM033R61C104KE84D" 0201_033 6716.04,441.02 r270 top
C44 "GRM1885C1H103JA01D" 0603 6705.5,302 r180 bottom
D1 "1N4148W-7-F" SOD-123 5374.47,240.72 r180 top
D2 "TPD1E05U06QDPYRQ1" DPY0002A 6404.97,832.15 r90 top
D3 "TPD1E01B04DPLR" DPL0002A 6792.77,661.37 r90 bottom
D4 "TPD1E01B04DPLR" DPL0002A 6935,747.42 r270 bottom
D5 "LP M67K-D2G1-25-Z" LP-M67K_Green 5985,410 r0 top
D6 "1N4148W-7-F" SOD-123 4988.22,240.72 r180 top
Designator2 "Comment" BRAKE_WAY_HOLES1X3 7189.29,3346.79 r90 top
Designator2_1 "Comment" BRAKE_WAY_HOLES1X3 -39.29,417.76 r270 top
Designator3 "Comment" BRAKE_WAY_HOLES1X3 7189.29,2212.03 r90 top
Designator3_1 "Comment" BRAKE_WAY_HOLES1X3 -41.15,1552.52 r270 top
Designator4 "Comment" BRAKE_WAY_HOLES1X3 7188.88,1130.65 r90 top
Designator4_1 "Comment" BRAKE_WAY_HOLES1X3 -38.88,2633.9 r270 top
Designator5 "Comment" BRAKE_WAY_HOLES1X3 7189.29,340.36 r90 top
Designator5_1 "Comment" BRAKE_WAY_HOLES1X3 -40.39,3424.19 r270 top
Designator59_3_1_2 "Comment" FID_40X80 -216.54,3408.55 r180 top
Designator59_3_1_2_1 "Comment" FID_40X80 -216.53,355.99 r0 top
Designator59_3_1_2_2 "Comment" FID_40X80 7366.38,355.99 r0 top
Designator59_3_1_2_3 "Comment" FID_40X80 7366.37,3408.55 r180 top
Designator64_2_1_2 "Comment" FID_40X80 -216.54,3408.55 r0 bottom
Designator64_2_1_2_1 "Comment" FID_40X80 -216.53,355.99 r180 bottom
Designator64_2_1_2_2 "Comment" FID_40X80 7366.38,355.99 r180 bottom
Designator64_2_1_2_3 "Comment" FID_40X80 7366.37,3408.55 r0 bottom
Designator69_2 "Comment" MHNP_M3_PANHEAD_PHILLIPS#1 -216.54,3564.55 r0 bottom
Designator69_2_1 "Comment" MHNP_M3_PANHEAD_PHILLIPS#1 -216.53,200 r180 bottom
Designator69_2_2 "Comment" MHNP_M3_PANHEAD_PHILLIPS#1 7366.38,200 r180 bottom
Designator69_2_3 "Comment" MHNP_M3_PANHEAD_PHILLIPS#1 7366.37,3564.55 r0 bottom
FB3 "BLM18EG121SN1D" FP-BLM18EG121SN1D_0603-MFG 5645.5,3567.82 r0 bottom
FB4 "BLM18EG121SN1D" FP-BLM18EG121SN1D_0603-MFG 5603.43,655 r180 top
FB5 "BLM18EG121SN1D" FP-BLM18EG121SN1D_0603-MFG 4043.03,682.92 r0 top
FB6 "BLM18EG121SN1D" FP-BLM18EG121SN1D_0603-MFG 5746.82,381.31 r270 top
FID1 "Fiducial" Fiducial10-20 100,3264 r0 top
FID2 "Fiducial" Fiducial10-20 7050,3263.02 r0 top
FID3 "Fiducial" Fiducial10-20 200,500 r0 top
FID4 "Fiducial" Fiducial10-20 100,3264 r180 bottom
FID5 "Fiducial" Fiducial10-20 200,500 r180 bottom
FID6 "Fiducial" Fiducial10-20 7050,3263.02 r180 bottom
J1 "HSEC8-130-01-L-DV-A" controlCARD-180HSEC-60pinAddon 4800,1784 r0 top locked
J2 "HSEC8-160-01-L-DV-A-BL" controlCARD-120HSEC 2449.17,1781.79 r0 top locked
J3 "22284033" Molex_0022284033 4459.94,123.67 r180 top
J4 "TSW-102-08-G-S" Samtec_TSW-102-08-x-S 5630.35,368.23 r90 top
J5 "22284033" Molex_0022284033 4121.41,123.67 r180 top
J6 "TSW-117-23-T-S" FP-TSW-117-23-T-S-MFG 1135,1239 r0 top
J7 "22284033" Molex_0022284033 5238.62,123.66 r180 top
J8 "22284033" Molex_0022284033 4863.69,125 r180 top
J9 "Receptacle_30x2_4MP_LeftRight" Samtec_QSH-030-01-X-D-A 4432.27,3260.09 r90 top
J10 "TSM-107-01-L-DV" Samtec_TSM-107-01-x-DV 4430,3254.2 r270 bottom
J11 "2012670005" FP-2012670005_CONN_USB_9MM39_8MM21-MFG 6980,710 r90 top
J12 "TSW-115-23-T-S" FP-TSW-115-23-T-S-MFG 1035,2329 r0 top
J13 "TSW-102-08-G-S" Samtec_TSW-102-08-x-S 6752.87,1759.98 r90 top
J14 "TSW-117-23-T-S" FP-TSW-117-23-T-S-MFG 1135,1079 r0 top
J15 "TSW-115-23-T-S" FP-TSW-115-23-T-S-MFG 1035,2489 r0 top
J16 "TSW-102-08-G-S" Samtec_TSW-102-08-x-S 6946.42,1759.98 r90 top
J17 "TSW-102-08-G-S" Samtec_TSW-102-08-x-S 6113.46,193.66 r90 top
J18 "22284033" Molex_0022284033 611.85,560.53 r0 top
J19 "TSW-102-08-G-S" Samtec_TSW-102-08-x-S 5902.46,193.66 r90 top
J20 "TSW-132-23-T-S" FP-TSW-132-23-T-S-MFG 2983.54,829 r0 top locked
J21 "TSW-133-23-T-S" FP-TSW-133-23-T-S-MFG 3007.95,2739 r0 top
J22 "22284033" Molex_0022284033 1370,549.3 r180 top
J23 "TSW-102-08-G-S" Samtec_TSW-102-08-x-S 6741.81,2705.22 r270 top
J24 "TSW-127-23-T-S" FP-TSW-127-23-T-S-MFG 5415,1244 r0 top
J25 "TSW-128-23-T-S" FP-TSW-128-23-T-S-0 5465,2279 r0 top
J26 "TSW-102-08-G-S" Samtec_TSW-102-08-x-S 6930,2700.22 r270 top
J27 "TSW-102-08-G-S" Samtec_TSW-102-08-x-S 635,2769 r270 top
J28 "TSW-102-08-G-S" Samtec_TSW-102-08-x-S 395,2774 r270 top
J29 "TSW-102-08-G-S" Samtec_TSW-102-08-x-S 2466.37,254.94 r270 top
J30 "TSW-102-08-G-S" Samtec_TSW-102-08-x-S 2251.37,259.94 r270 top
J31 "TSW-101-08-G-S" Samtec_TSW-101-08-x-S 4240.07,2901.87 r0 top
J32 "TSW-101-08-G-S" Samtec_TSW-101-08-x-S 3974.04,2921.24 r0 top
J33 "TSW-101-08-G-S" Samtec_TSW-101-08-x-S 4544.29,721.89 r0 top
J34 "TSW-101-08-G-S" Samtec_TSW-101-08-x-S 3280.29,2889 r0 top
J35 "TSW-101-08-G-S" Samtec_TSW-101-08-x-S 3583.54,629 r0 top
J36 "TSW-101-08-G-S" Samtec_TSW-101-08-x-S 2227.12,2889 r0 top
J37 "TSW-101-08-G-S" Samtec_TSW-101-08-x-S 2383.54,629 r0 top
J38 "TSW-101-08-G-S" Samtec_TSW-101-08-x-S 3631.35,2889 r0 top
J39 "TSW-101-08-G-S" Samtec_TSW-101-08-x-S 2983.54,508.47 r0 top
J40 "TSW-101-08-G-S" Samtec_TSW-101-08-x-S 2578.17,2889 r0 top
J41 "TSW-101-08-G-S" Samtec_TSW-101-08-x-S 1583.54,629 r0 top
J42 "TSW-101-08-G-S" Samtec_TSW-101-08-x-S 1882.4,2881.6 r0 top
J43 "TSW-101-08-G-S" Samtec_TSW-101-08-x-S 3985,570 r0 top
J44 "TSW-101-08-G-S" Samtec_TSW-101-08-x-S 2929.23,2889 r0 top
J45 "TSW-101-08-G-S" Samtec_TSW-101-08-x-S 3183.54,629 r0 top
J46 "TSW-101-08-G-S" Samtec_TSW-101-08-x-S 1401.7,2894.3 r0 top
J47 "TSW-101-08-G-S" Samtec_TSW-101-08-x-S 2783.54,629 r0 top
J48 "TSW-101-08-G-S" Samtec_TSW-101-08-x-S 6795,2486.7 r0 top
J49 "TSW-101-08-G-S" Samtec_TSW-101-08-x-S 1983.54,629 r0 top
J50 "TSW-101-08-G-S" Samtec_TSW-101-08-x-S 5933.69,1104 r0 top
J51 "TSW-101-08-G-S" Samtec_TSW-101-08-x-S 6417.9,2486.7 r0 top
J52 "TSW-101-08-G-S" Samtec_TSW-101-08-x-S 6601.04,1104 r0 top
J53 "TSW-101-08-G-S" Samtec_TSW-101-08-x-S 5680.2,2482.22 r0 top
J54 "TSW-101-08-G-S" Samtec_TSW-101-08-x-S 5266.33,1104 r0 top
J55 "TSW-101-08-G-S" Samtec_TSW-101-08-x-S 4920.31,2482.99 r0 top
J56 "TSW-101-08-G-S" Samtec_TSW-101-08-x-S 5600.01,1104 r0 top
J57 "TSW-101-08-G-S" Samtec_TSW-101-08-x-S 4155.27,2486.7 r0 top
J58 "TSW-101-08-G-S" Samtec_TSW-101-08-x-S 6267.37,1104 r0 top
J59 "TSW-101-08-G-S" Samtec_TSW-101-08-x-S 6044.93,2493.36 r0 top
J60 "TSW-101-08-G-S" Samtec_TSW-101-08-x-S 4598.98,1104 r0 top
J61 "TSW-101-08-G-S" Samtec_TSW-101-08-x-S 5246.86,2487.85 r0 top
J62 "TSW-101-08-G-S" Samtec_TSW-101-08-x-S 4932.66,1104 r0 top
J63 "TSW-101-08-G-S" Samtec_TSW-101-08-x-S 4532.38,2486.7 r0 top
J64 "TSW-101-08-G-S" Samtec_TSW-101-08-x-S 4265.3,1104 r0 top
J65 "TSW-102-08-G-S" Samtec_TSW-102-08-x-S 725.16,847.74 r0 top
J66 "TSW-102-08-G-S" Samtec_TSW-102-08-x-S 1229.46,852.31 r180 top
L1 "TFM201610ALMA2R2MTAA" TFM201610ALMA 5696.11,782.9 r270 top
Logo1 "CE Mark" CE_Mark_5mm 1485,3162 r0 top
Logo2 "Texas Instruments" TI_Stacked_Overlay_Small 1709,3399 r0 top
Logo3 "FCC disclaimer" FCC_disclaimer -65.04,3068.5 r90 top
Logo4 "WEEE logo" WEEE_Minimum 958.54,2840.61 r0 top
MHNP1 "Comment" MHNP_M3_PANHEAD_PHILLIPS#2 7000,150 r180 top
MHNP2 "Comment" MHNP_M3_PANHEAD_PHILLIPS#2 150,150 r90 top
MHNP3 "Comment" MHNP_M3_PANHEAD_PHILLIPS#2 150,3614 r0 top
MHNP4 "Comment" MHNP_M3_PANHEAD_PHILLIPS#2 7000,3614 r270 top
MHNP5 "Comment" MHNP_M3_PANHEAD_PHILLIPS#2 3415,3614 r0 top
MHNP6 "Comment" MHNP_M3_PANHEAD_PHILLIPS#2 3415,150 r0 top
MOD1 "MSPL_GPMC_MOD" MSPL_GPMC_MOD 5759.29,3265.66 r0 top locked
Q1 "BSS138LT1G" ONSC-SOT-23-3-318-08_V 6130.63,437.4 r180 top
R1 "CRCW040259R0FKED" 0402 4514.9,248.46 r180 top
R2 "CRCW040259R0FKED" 0402 4404.9,248.46 r180 top
R3 "CRCW04020000Z0ED" 0402 4438.92,694.73 r270 top
R4 "CRCW040233R0JNED" 0402 4285.8,688.47 r270 top
R5 "CRCW040259R0FKED" 0402 4176.38,248.46 r180 top
R6 "CRCW04020000Z0ED" 0402 4233.03,687.09 r270 top
R7 "CRCW040233R0JNED" 0402 4013.71,456.6 r0 top
R8 "ERJ-2GEJ103X" 0402 4552.4,461.6 r180 top
R9 "ERJ-2GEJ103X" 0402 4291.3,265 r90 top
R10 "CRCW040259R0FKED" 0402 4066.38,248.46 r180 top
R11 "CRCW0402110RJNED" 0402 5750.74,3443.08 r90 bottom
R12 "CRCW040222R0JNED" 0402 5550.01,3066.28 r270 bottom
R13 "CRCW040210K0JNED" 0402 5809.01,2514 r270 top
R14 "CRCW040210K0JNED" 0402 5851.61,2513.36 r270 top
R15 "CRCW0201100RFKED" 0201 4081.19,3024.19 r270 top
R16 "CRCW0201100RFKED" 0201 4223.99,3477.51 r90 top
R17 "CRCW02014K70FKED" 0201_033 4186.1,3477.51 r90 top
R18 "ERJ-1GNF33R2C" FP-ERJ-1GNF33R2C_0201-IPC_B 4122.92,3634.74 r0 top
R19 "ERJ-1GNF33R2C" FP-ERJ-1GNF33R2C_0201-IPC_B 4122.5,3029.51 r270 top
R20 "CRCW040210K0JNED" 0402 5767.99,2514.34 r90 top
R21 "ERJ-1GNF33R2C" FP-ERJ-1GNF33R2C_0201-IPC_B 4167.39,3028.53 r270 top
R22 "CRCW040210K0JNED" 0402 5895.27,2513.57 r90 top
R23 "CRCW0201100RFKED" 0201 4329.6,3529.99 r90 bottom
R24 "RC0201FR-0710RL" 0201 2694.96,2046.49 r90 top
R25 "CRCW02010000Z0ED" 0201 4045.41,3024.65 r90 top
R26 "RC0201FR-0710RL" 0201 2726.45,2045.49 r90 top
R27 "RC0201FR-0710RL" 0201 4339.35,1547.99 r90 top
R28 "RC0201FR-0710RL" 0201 4325,2024 r90 top
R29 "RC0201FR-0710RL" 0201 4361.43,2024 r90 top
R30 "RC0201FR-0710RL" 0201 4378.37,1547.99 r90 top
R31 "RC0201FR-0710RL" 0201 4397.86,2024 r90 top
R32 "RC0201FR-0710RL" 0201 4417.4,1547.99 r90 top
R33 "RC0201FR-0710RL" 0201 4434.29,2024 r90 top
R34 "RC0201FR-0710RL" 0201 4456.43,1547.99 r90 top
R35 "RC0201FR-0710RL" 0201 4470.71,2024 r90 top
R36 "CRCW04021K00FKED" 0402 5515,246.22 r270 top
R37 "CRCW040210K0JNED" 0402 4429.6,3555.62 r270 bottom
R38 "CRCW040210K0JNED" 0402 4224.6,3553.38 r270 bottom
R39 "CRCW040210K0JNED" 0402 4134.6,3553.38 r270 bottom
R40 "RC0201FR-0710RL" 0201 4495.46,1547.99 r90 top
R41 "RC0201FR-0710RL" 0201 4507.14,2024 r90 top
R42 "RC0201FR-0710RL" 0201 4534.48,1547.99 r90 top
R43 "RC0201FR-0710RL" 0201 4543.57,2024 r90 top
R44 "RC0201FR-0710RL" 0201 4573.51,1547.99 r90 top
R45 "RC0201FR-0710RL" 0201 4580,2024 r90 top
R46 "RC0201FR-0710RL" 0201 4612.54,1547.99 r90 top
R47 "ERJ-1GNJ220C" 0201 4204.97,3025.08 r90 top
R48 "CRCW040222R0JNED" 0402 5604.8,3066.28 r270 bottom
R49 "ERJ-2RKF4701X" 0402 6557.59,395.31 r90 top
R50 "ERJ-2RKF4701X" 0402 6557.59,505.2 r270 top
R51 "ERJ-6ENF9093V" 0805_HV 6425.4,306.34 r90 top
R52 "CRCW06034K70JNEA" 0603 6346,320.2 r270 top
R53 "CRCW04020000Z0ED" 0402 6474.01,540.03 r180 top
R54 "ERJ-2RKF2003X" 0402 6500,329.69 r90 top
R55 "CRCW0603220RJNEA" 0603 5851.5,410.07 r180 top
R56 "CRCW04020000Z0ED" 0402 6245,375 r270 top
R57 "CRCW12061M00FKEA" 1206 6934.71,377.36 r180 bottom
R58 "CRCW0402100KFKED" 0402 5746.82,913.57 r90 top
R59 "CRCW040222R0JNED" 0402 5659.59,3066.28 r270 bottom
R60 "CRCW040222R0JNED" 0402 5714.38,3066.28 r270 bottom
R61 "CRCW040222R0JNED" 0402 5769.17,3066.28 r270 bottom
R62 "CRCW040222R0JNED" 0402 5823.95,3066.28 r270 bottom
R63 "CRCW040222R0JNED" 0402 5878.74,3066.28 r270 bottom
R64 "CRCW040222R0JNED" 0402 6025.28,3134.19 r0 bottom
R65 "CRCW040222R0JNED" 0402 5593.58,3461.25 r90 bottom
R66 "CRCW040222R0JNED" 0402 5685.09,3461.37 r90 bottom
R67 "CRCW040222R0JNED" 0402 5643.28,3461.25 r90 bottom
R68 "CRCW040222R0JNED" 0402 5531.88,3454.83 r270 bottom
R69 "CRCW040222R0JNED" 0402 5892.49,3438.83 r0 bottom
R70 "CRCW040222R0JNED" 0402 5999.82,3339.05 r0 bottom
R71 "CRCW040222R0JNED" 0402 5999.84,3438.29 r0 bottom
R72 "CRCW040222R0JNED" 0402 5999.26,3388.88 r0 bottom
R73 "CRCW040210K0JNED" 0402 5527.52,3176.5 r180 bottom
R74 "CRCW040210K0JNED" 0402 5933.53,3066.28 r270 bottom
R75 "CRCW040210K0JNED" 0402 5527.62,3250.4 r180 bottom
R76 "CRCW040210K0JNED" 0402 5527.62,3373.4 r180 bottom
R77 "CRCW040210K0JNED" 0402 5527.62,3311.9 r180 bottom
R78 "CRCW040210K0JNED" 0402 5495.22,3066.28 r270 bottom
R79 "CRCW040210K0JNED" 0402 2359.29,3438.96 r180 top
R80 "CRCW040210K0JNED" 0402 2450.67,3339.55 r180 top
R81 "CRCW040210K0JNED" 0402 4531,3555.08 r270 bottom
R82 "CRCW040210K0JNED" 0402 2767.9,3174.3 r90 top
R83 "CRCW040210K0JNED" 0402 2596.02,3115.05 r0 top
R84 "CRCW04021K00FKED" 0402 5132.72,246.22 r270 top
R85 "CRCW040210K0JNED" 0402 5315.34,963.62 r90 top
R86 "CRCW040210K0JNED" 0402 5054.88,963.16 r90 top
R87 "CRCW040210K0JNED" 0402 5207.87,963.62 r270 top
R88 "CRCW040233R0JNED" 0402 5262.77,963.62 r270 top
R89 "CRCW04020000Z0ED" 0402 5159.37,963.62 r270 top
R90 "CRCW040210K0JNED" 0402 4999.88,963.16 r270 top
R91 "CRCW040233R0JNED" 0402 5106.88,962.24 r270 top
R92 "CRCW04020000Z0ED" 0402 4945.86,963.16 r270 top
R93 "CRCW040210K0JNED" 0402 6214.01,856.46 r270 top
R94 "CRCW0402100KFKED" 0402 6712.29,369 r0 bottom
R95 "PTV09A-8025U-B103" FP-PTV09A-8025U-B103_PTH_POT_27MM4_9MM7-MFG 611.85,-160.17 r0 top
R96 "PTV09A-8025U-B103" FP-PTV09A-8025U-B103_PTH_POT_27MM4_9MM7-MFG 1376.57,-160.17 r0 top
R97 "RC0201FR-0710RL" 0201 4616.63,2022.99 r90 top
R98 "RC0201FR-0710RL" 0201 4651.56,1547.99 r90 top
R99 "RC0201FR-0710RL" 0201 4651.56,2022.99 r90 top
R100 "RC0201FR-0710RL" 0201 4689.76,1548.5 r90 top
R101 "RC0201FR-0710RL" 0201 4686.5,2022.99 r90 top
R102 "RC0201FR-0710RL" 0201 4724.26,1548.5 r90 top
R103 "RC0201FR-0710RL" 0201 4721.43,2022.99 r90 top
R104 "RC0201FR-0710RL" 0201 4758.75,1548.5 r90 top
R105 "RC0201FR-0710RL" 0201 4756.36,2022.99 r90 top
R106 "RC0201FR-0710RL" 0201 4793.25,1548.5 r90 top
R107 "RC0201FR-0710RL" 0201 4791.3,2022.99 r90 top
R108 "RC0201FR-0710RL" 0201 4827.74,1548.5 r90 top
R109 "RC0201FR-0710RL" 0201 4826.23,2022.99 r90 top
R110 "RC0201FR-0710RL" 0201 4862.23,1548.5 r90 top
R111 "RC0201FR-0710RL" 0201 4861.16,2022.99 r90 top
R112 "RC0201FR-0710RL" 0201 4896.73,1548.5 r90 top
R113 "RC0201FR-0710RL" 0201 4896.1,2022.99 r90 top
R114 "RC0201FR-0710RL" 0201 4931.22,1548.5 r90 top
R115 "RC0201FR-0710RL" 0201 4931.03,2022.99 r90 top
R116 "RC0201FR-0710RL" 0201 4965.72,1548.5 r90 top
R117 "RC0201FR-0710RL" 0201 4965.97,2022.99 r90 top
R118 "RC0201FR-0710RL" 0201 5000.21,1548.5 r90 top
R119 "RC0201FR-0710RL" 0201 5000.9,2022.99 r90 top
R120 "RC0201FR-0710RL" 0201 5034.71,1548.5 r90 top
R121 "RC0201FR-0710RL" 0201 5035.83,2022.99 r90 top
R122 "RC0201FR-0710RL" 0201 5069.2,1548.5 r90 top
R123 "RC0201FR-0710RL" 0201 5070.77,2022.99 r90 top
R124 "RC0201FR-0710RL" 0201 5103.69,1548.5 r90 top
R125 "RC0201FR-0710RL" 0201 5105.7,2022.99 r90 top
S1 "CAS-120TA" SW_CAS-120TA 5698.22,155.28 r270 top
SH-J1 "60900213421" Wurth_60900213421 334.92,560.53 r180 top
SH-J2 "60900213421" Wurth_60900213421 1629.92,494.18 r180 top
SH-J3 "60900213421" Wurth_60900213421 491.8,841.83 r180 top
SH-J4 "60900213421" Wurth_60900213421 1361.32,957.95 r180 top
SW1 "A6TN-1104" FP-A6TN-1104_PTH_SW_7MM50_4MM48-MFG 5345,420 r270 top
SW2 "A6TN-1104" FP-A6TN-1104_PTH_SW_7MM50_4MM48-MFG 4891.02,412.09 r270 top
SW3 "200AWMSP1T1A1M2QE" FP-200AWMSP1T1A1M2QE_PTH_SW_8MM13_5MM08-MFG 6661,156 r180 top
U1 "TCAN1046DRQ1" D0014A_N 4290.64,487.26 r270 top
U2 "TLIN2022DRQ1" D0014A_N 5111.97,732.45 r270 top
U3 "IS67WVE4M16EBLL-70BLA1" FP-IS67WVE4M16EBLL-70BLA1_TFBGA48-IPC_C 5759.29,3265.71 r270 bottom
U4 "TS3DDR3812RUAR" RUA0042A-MFG 5898.72,2691.88 r90 bottom
U5 "TS3DDR3812RUAR" RUA0042A-MFG 4964.12,2691.88 r90 bottom
U6 "TS3DDR3812RUAR" RUA0042A-MFG 6366.02,2691.88 r90 bottom
U7 "TS3DDR3812RUAR" RUA0042A-MFG 5431.42,2691.88 r90 bottom
U8 "TUSB320IRWBR" RWB0012A 6440.59,445.94 r0 top
U9 "SN74AHC1G02DRLR" DRL0005A 6651.13,440.68 r0 top
U10 "TPS22965DSGT" FP-DSG0008A-MFG 6116.82,807.24 r180 top
U11 "TPS62172DSGT" DSG0008A 5834.41,812.07 r180 top
U12 "SN74CB3Q3257PWR" PW0016A_L 2947.91,3195.93 r0 top
U13 "SN74LVC1G04DCKR" DCK0005A_N 2495,3438.96 r0 top
U14 "SN74LVC1G08DSF2" DSF0006A 2553.54,3343.33 r0 top
U15 "SN74AHC1G02DBVT" DBV0005A_N 2430.16,3152.15 r0 top
U16 "OPA2837DGK" DGK0008A_N 972.76,739.51 r0 top
U18 "SN74LVC1G08DSF2" DSF0006A 6755.96,431.4 r90 bottom
ZZ1 "This Assembly Note is for PCB labels only" AssemblyNoteLabel 185,3938 r0 top
ZZ2 "These assemblies are ESD sensitive, ESD precautions shall be observed." AssemblyNote 185,3829.11 r0 top
ZZ3 "These assemblies must be clean and free from flux and all contaminants. Use of no clean flux is not acceptable." AssemblyNote 310,3925.56 r0 top
ZZ4 "These assemblies must comply with workmanship standards IPC-A-610 Class 2, unless otherwise specified." AssemblyNote 310,3837 r0 top

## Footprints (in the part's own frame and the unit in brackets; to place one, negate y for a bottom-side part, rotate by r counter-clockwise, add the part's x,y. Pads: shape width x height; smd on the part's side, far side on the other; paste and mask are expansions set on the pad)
0201 [mm] "Data from Kemet datasheet CC101_COM dated 7/28/11"
  rect 0.46x0.42 smd mask+0: 1(-0.33,0) 2(0.33,0)
0201_033 [mm] "SMD, 2-Leads, Height 0.33mm"
  rect 0.46x0.42 smd mask+0: 1(-0.33,0) 2(0.33,0)
0402 [mm] "0402 from SM-752 data"
  rect 0.8x0.6 smd: 1(-0.6,0) 2(0.6,0)
  silkscreen extent -1.22,-0.52 1.22,0.52
0603 [mm] "0603 from SM-752 data"
  rect 1x0.95 smd: 1(-0.8,0) 2(0.8,0)
  silkscreen extent -1.52,-0.69 1.52,0.69
0805_HV [mil] "0805 with 30mil clearance between pads"
  rect 50x63 smd: 1(-40,0) 2(40,0)
  silkscreen extent -74,-40 74,40
1206 [mm] "1206 from SM-752 data"
  rect 1.3x1.85 smd: 1(-1.45,0) 2(1.45,0)
  silkscreen extent -2.4,-1.21 2.4,1.21
1206_180 [mm] "1206_180"
  rect 1.1x1.6 smd: 1(-1.7,0) 2(1.7,0)
  silkscreen extent -0.9,-1 0.9,1
1210_270 [mm] "1210"
  rect 1.3x2.7 smd: 1(-1.45,0) 2(1.45,0)
  silkscreen extent -2.32,-1.57 2.32,1.57
1210_280 [mm] "SMD, 2-Leads, Body 3.6x2.8mm, Height 2.8mm"
  rect 1.1x2.2 smd: 1(-1.65,0) 2(1.65,0)
  silkscreen extent -0.84,-1.4 0.84,1.4
1808 [mm] "Chip Capacitor, Body 4.6x2.0mm, IPC Medium Density"
  rect 1.4x2.3 smd: 1(-2.1,0) 2(2.1,0)
  silkscreen extent -3.1,-1.45 3.1,1.45
AssemblyNote [mil] "Assembly Note"
AssemblyNoteLabel [mil] "Assembly Note for PCB Labels"
BRAKE_WAY_HOLES1X3 [mil]
  round 27 hole 32 unplated mask+0: ""(-50,49.37) ""(0,49.37) ""(50,49.37)
CE_Mark_5mm [mil] "Minimum text height for CE Mark"
controlCARD-120HSEC [mm] "Pads are not numbered according to Samtec datasheet."
  rect 0.5x2.724 smd: 1(-23.357,-1.678) 2(-23.357,1.722) 3(-22.557,-1.678) 4(-22.557,1.722) 5(-21.757,-1.678) 6(-21.757,1.722) 7(-20.957,-1.678) 8(-20.957,1.722) 9(-20.157,-1.678) 10(-20.157,1.722) 11(-19.357,-1.678) 12(-19.357,1.722) 13(-18.557,-1.678) 14(-18.557,1.722) 15(-17.757,-1.678) 16(-17.757,1.722) 17(-16.957,-1.678) 18(-16.957,1.722) 19(-16.157,-1.678) 20(-16.157,1.722) 21(-15.357,-1.678) 22(-15.357,1.722) 23(-14.557,-1.678) 24(-14.557,1.722) 25(-13.757,-1.678) 26(-13.757,1.722) 27(-12.957,-1.678) 28(-12.957,1.722) 29(-12.157,-1.678) 30(-12.157,1.722) 31(-11.357,-1.678) 32(-11.357,1.722) 33(-10.557,-1.678) 34(-10.557,1.722) 35(-9.757,-1.678) 36(-9.757,1.722) 37(-8.957,-1.678) 38(-8.957,1.722) 39(-8.157,-1.678) 40(-8.157,1.722) 41(-7.357,-1.678) 42(-7.357,1.722) 43(-6.557,-1.678) 44(-6.557,1.722) 45(-5.757,-1.678) 46(-5.757,1.722) 47(-4.957,-1.678) 48(-4.957,1.722) 49(-4.157,-1.678) 50(-4.157,1.722) 51(-3.357,-1.678) 52(-3.357,1.722) 53(-2.557,-1.678) 54(-2.557,1.722) 55(-1.757,-1.678) 56(-1.757,1.722) 57(2.243,-1.678) 58(2.243,1.722) 59(3.043,-1.678) 60(3.043,1.722) 61(3.843,-1.678) 62(3.843,1.722) 63(4.643,-1.678) 64(4.643,1.722) 65(5.443,-1.678) 66(5.443,1.722) 67(6.243,-1.678) 68(6.243,1.722) 69(7.043,-1.678) 70(7.043,1.722) 71(7.843,-1.678) 72(7.843,1.722) 73(8.643,-1.678) 74(8.643,1.722) 75(9.443,-1.678) 76(9.443,1.722) 77(10.243,-1.678) 78(10.243,1.722) 79(11.043,-1.678) 80(11.043,1.722) 81(11.843,-1.678) 82(11.843,1.722) 83(12.643,-1.678) 84(12.643,1.722) 85(13.443,-1.678) 86(13.443,1.722) 87(14.243,-1.678) 88(14.243,1.722) 89(15.043,-1.678) 90(15.043,1.722) 91(15.843,-1.678) 92(15.843,1.722) 93(16.643,-1.678) 94(16.643,1.722) 95(17.443,-1.678) 96(17.443,1.722) 97(18.243,-1.678) 98(18.243,1.722) 99(19.043,-1.678) 100(19.043,1.722) 101(19.843,-1.678) 102(19.843,1.722) 103(20.643,-1.678) 104(20.643,1.722) 105(21.443,-1.678) 106(21.443,1.722) 107(22.243,-1.678) 108(22.243,1.722) 109(23.043,-1.678) 110(23.043,1.722) 111(23.843,-1.678) 112(23.843,1.722) 113(24.643,-1.678) 114(24.643,1.722) 115(25.443,-1.678) 116(25.443,1.722) 117(26.243,-1.678) 118(26.243,1.722) 119(27.043,-1.678) 120(27.043,1.722)
  round 0.025 hole 1.27 unplated mask+0: 181(-24.857,0.022) 182(28.543,1.522)
  round 1.348 hole 0.84: 185(-27.207,0.022) 186(30.893,0.022)
  silkscreen extent -32.11,-3.86 35.8,3.9
controlCARD-180HSEC-60pinAddon [mm] "Pads are not numbered according to datasheet."
  round 0.025 hole 1.27 unplated mask+0: 61(-13.1,0) 62(13.1,1.5)
  rect 0.5x2.724 smd: 121(-11.6,-1.7) 122(-11.6,1.7) 123(-10.8,-1.7) 124(-10.8,1.7) 125(-10,-1.7) 126(-10,1.7) 127(-9.2,-1.7) 128(-9.2,1.7) 129(-8.4,-1.7) 130(-8.4,1.7) 131(-7.6,-1.7) 132(-7.6,1.7) 133(-6.8,-1.7) 134(-6.8,1.7) 135(-6,-1.7) 136(-6,1.7) 137(-5.2,-1.7) 138(-5.2,1.7) 139(-4.4,-1.7) 140(-4.4,1.7) 141(-3.6,-1.7) 142(-3.6,1.7) 143(-2.8,-1.7) 144(-2.8,1.7) 145(-2,-1.7) 146(-2,1.7) 147(-1.2,-1.7) 148(-1.2,1.7) 149(-0.4,-1.7) 150(-0.4,1.7) 151(0.4,-1.7) 152(0.4,1.7) 153(1.2,-1.7) 154(1.2,1.7) 155(2,-1.7) 156(2,1.7) 157(2.8,-1.7) 158(2.8,1.7) 159(3.6,-1.7) 160(3.6,1.7) 161(4.4,-1.7) 162(4.4,1.7) 163(5.2,-1.7) 164(5.2,1.7) 165(6,-1.7) 166(6,1.7) 167(6.8,-1.7) 168(6.8,1.7) 169(7.6,-1.7) 170(7.6,1.7) 171(8.4,-1.7) 172(8.4,1.7) 173(9.2,-1.7) 174(9.2,1.7) 175(10,-1.7) 176(10,1.7) 177(10.8,-1.7) 178(10.8,1.7) 179(11.6,-1.7) 180(11.6,1.7)
  silkscreen extent -14.68,-3.88 14.68,3.88
D0014A_N [mm] "SOIC, 14-Leads, Body 8.7x3.9mm, Pitch 1.27mm, IPC Medium Density"
  oval 1.45x0.6 smd: 1(-2.725,3.81) 2(-2.725,2.54) 3(-2.725,1.27) 4(-2.725,0) 5(-2.725,-1.27) 6(-2.725,-2.54) 7(-2.725,-3.81) 8(2.725,-3.81) 9(2.725,-2.54) 10(2.725,-1.27) 11(2.725,0) 12(2.725,1.27) 13(2.725,2.54) 14(2.725,3.81)
  silkscreen extent -3.3,-4.4 0.9,4.4
DBV0005A_N [mm] "SOT23, 5-Leads, Body 2.9x1.6mm, Pitch 0.95mm, Lead Span 2.8mm, IPC Medium Density"
  rrect17% 1x0.6 smd: 1(-1.375,0.95) 2(-1.375,0) 3(-1.375,-0.95) 4(1.375,-0.95) 5(1.375,0.95)
  silkscreen extent -1.63,-1.55 0.38,1.55
DCK0005A_N [mm] "SOT353, 5-Leads, Body 2x1.3mm, Pitch 0.65mm, Lead Span 2.1mm, IPC Medium Density"
  rrect25% 0.85x0.4 smd: 1(-1.125,0.65) 2(-1.125,0) 3(-1.125,-0.65) 4(1.125,-0.65) 5(1.125,0.65)
  silkscreen extent -1.48,-1.02 0.55,1.1
DGK0008A_N [mm] "TSOP, 8-Leads, Body 3x3mm, Pitch 0.65mm, IPC Medium Density"
  oval 1.35x0.45 smd: 1(-2.225,0.975) 2(-2.225,0.325) 3(-2.225,-0.325) 4(-2.225,-0.975) 5(2.225,-0.975) 6(2.225,-0.325) 7(2.225,0.325) 8(2.225,0.975)
  silkscreen extent -2.75,-1.55 0.95,1.55
DPL0002A [mm] "R-PX2SON-N2"
  rect 0.18x0.25 smd: 1(-0.193,0)
  rect 0.19x0.25 smd: 2(0.192,0)
DPY0002A [mm] "X1SON-2"
  rrect57% 0.35x0.6 smd paste-0.5 mask+0: 1(-0.325,0) 2(0.325,0)
  rrect33% 0.3x0.5 on Top Paste: 1S(-0.35,0) 2S(0.35,0)
  silkscreen extent -0.85,-0.03 -0.8,0.02
DRL0005A [mm] "SOTFL, 5-Flat Leads, Body 1.2x1.6x0.6mm, Pitch 0.5mm, TI recommended"
  rrect33% 0.67x0.3 smd: 1(-0.74,0.5) 2(-0.74,0) 3(-0.74,-0.5) 4(0.74,-0.5) 5(0.74,0.5)
  silkscreen extent -0.9,-0.95 0.5,0.95
DSF0006A [mm] "TI recommended land pattern"
  rrect59% 0.6x0.17 smd mask+0: 1(-0.4,0.35) 2(-0.4,0) 3(-0.4,-0.35) 4(0.4,-0.35) 5(0.4,0) 6(0.4,0.35)
  silkscreen extent -0.6,-0.63 0.6,0.63
DSG0008A [mm] "SON, 8-Leads, Body 2x2mm, Pitch 0.5mm, Thermal Pad 1.6x0.9mm, TI Recommended"
  rrect40% 0.5x0.25 smd: 1(-0.95,0.75) 2(-0.95,0.25) 3(-0.95,-0.25) 4(-0.95,-0.75) 5(0.95,-0.75) 6(0.95,-0.25) 7(0.95,0.25) 8(0.95,0.75)
  rrect14% 0.9x0.7 on Top Paste: 9(0,0.45) 9(0,-0.45)
  rrect11% 0.9x1.6 smd paste-0.45: 9(0,0)
  silkscreen extent -1.07,-1.15 1.07,1.15
FCC_disclaimer [mil]
FID_40X80 [mil]
  round 40 smd paste-20 mask+0: ""(0,0)
  Top Layer keep-out circle w1: c0,0 r42.5
Fiducial10-20 [mm]
  round 1 smd mask+0: 1(0,0)
  Top Layer keep-out circle w1.178: c0,0 r0.5
FP-200AWMSP1T1A1M2QE_PTH_SW_8MM13_5MM08-MFG [mm]
  rrect6% 1.69x1.69 hole 1.09 paste-1000 mask+0: 1(-2.54,0)
  round 1.69 hole 1.09 paste-1000 mask+0: 2(0,0) 3(2.54,0)
  silkscreen extent -4.75,-2.67 4.19,2.67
